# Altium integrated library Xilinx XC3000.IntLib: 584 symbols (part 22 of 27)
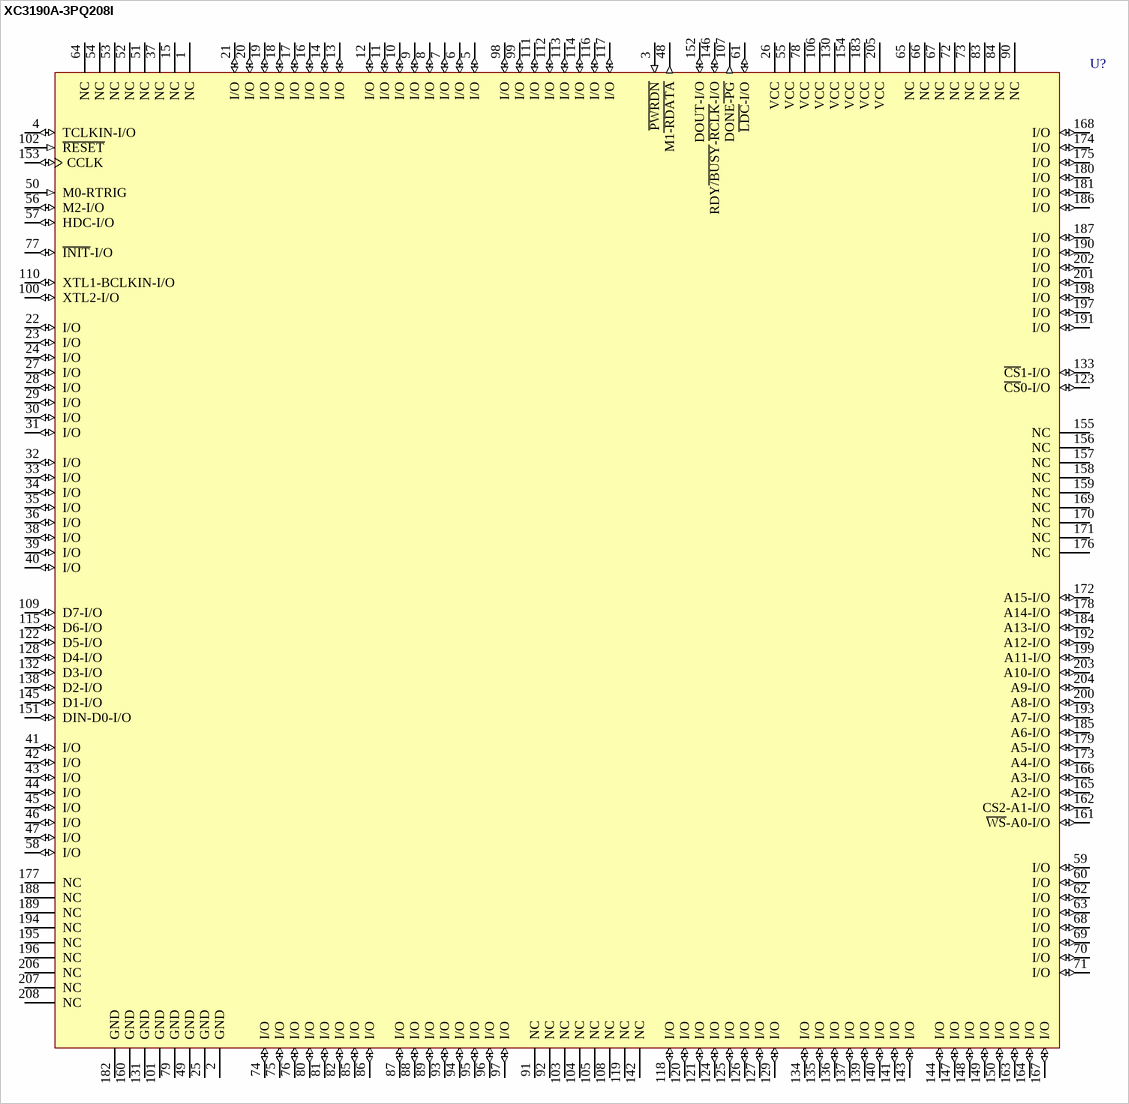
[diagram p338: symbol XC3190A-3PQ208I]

## XC3190A-3PQ208I
designator U?
Logic Cell Array with 320 CLBs, with 144 I/O Pins, 208-Pin PQFP, Industrial Grade; ComponentAvailability: Not for New Design
footprint PQ208_N (Shrink QFP, 208-Leads, Body 28x28mm, Pitch 0.5mm, IPC Medium Density)
footprint PQ208_L (Shrink QFP, 208-Leads, Body 28x28mm, Pitch 0.5mm, IPC High Density)
footprint PQ208_M (Shrink QFP, 208-Leads, Body 28x28mm, Pitch 0.5mm, IPC Low Density)
3D model XC3190A-PQ208 (208-Pin Plastic Quad Flat Pack (PQ208))
pins: 1 NC, 2 GND (power), 3 ~{PWRDN} (in), 4 TCLKIN-I/O (io), 5 I/O (io), 6 I/O (io), 7 I/O (io), 8 I/O (io), 9 I/O (io), 10 I/O (io), 11 I/O (io), 12 I/O (io), 13 I/O (io), 14 I/O (io), 15 NC, 16 I/O (io), 17 I/O (io), 18 I/O (io), 19 I/O (io), 20 I/O (io), 21 I/O (io), 22 I/O (io), 23 I/O (io), 24 I/O (io), 25 GND (power), 26 VCC (power), 27 I/O (io), 28 I/O (io), 29 I/O (io), 30 I/O (io), 31 I/O (io), 32 I/O (io), 33 I/O (io), 34 I/O (io), 35 I/O (io), 36 I/O (io), 37 NC, 38 I/O (io), 39 I/O (io), 40 I/O (io), 41 I/O (io), 42 I/O (io), 43 I/O (io), 44 I/O (io), 45 I/O (io), 46 I/O (io), 47 I/O (io), 48 M1~{-RDATA} (out), 49 GND (power), 50 M0-RTRIG (in), 51 NC, 52 NC, 53 NC, 54 NC, 55 VCC (power), 56 M2-I/O (io), 57 HDC-I/O (io), 58 I/O (io), 59 I/O (io), 60 I/O (io), 61 ~{LDC}-I/O (io), 62 I/O (io), 63 I/O (io), 64 NC, 65 NC, 66 NC, 67 NC, 68 I/O (io), 69 I/O (io), 70 I/O (io), 71 I/O (io), 72 NC, 73 NC, 74 I/O (io), 75 I/O (io), 76 I/O (io), 77 ~{INIT}-I/O (io), 78 VCC (power), 79 GND (power), 80 I/O (io), 81 I/O (io), 82 I/O (io), 83 NC, 84 NC, 85 I/O (io), 86 I/O (io), 87 I/O (io), 88 I/O (io), 89 I/O (io), 90 NC, 91 NC, 92 NC, 93 I/O (io), 94 I/O (io), 95 I/O (io), 96 I/O (io), 97 I/O (io), 98 I/O (io), 99 I/O (io), 100 XTL2-I/O (io), 101 GND (power), 102 ~{RESET} (in), 103 NC, 104 NC, 105 NC, 106 VCC (power), 107 DONE~{-PG} (out), 108 NC, 109 D7-I/O (io), 110 XTL1-BCLKIN-I/O (io), 111 I/O (io), 112 I/O (io), 113 I/O (io), 114 I/O (io), 115 D6-I/O (io), 116 I/O (io), 117 I/O (io), 118 I/O (io), 119 NC, 120 I/O (io), 121 I/O (io), 122 D5-I/O (io), 123 ~{CS}0-I/O (io), 124 I/O (io), 125 I/O (io), 126 I/O (io), 127 I/O (io), 128 D4-I/O (io), 129 I/O (io), 130 VCC (power), 131 GND (power), 132 D3-I/O (io), 133 ~{CS}1-I/O (io), 134 I/O (io), 135 I/O (io), 136 I/O (io), 137 I/O (io), 138 D2-I/O (io), 139 I/O (io), 140 I/O (io), 141 I/O (io), 142 NC, 143 I/O (io), 144 I/O (io), 145 D1-I/O (io), 146 RDY~{/BUSY}-~{RCLK}-I/O (io), 147 I/O (io), 148 I/O (io), 149 I/O (io), 150 I/O (io), 151 DIN-D0-I/O (io), 152 DOUT-I/O (io), 153 CCLK (io), 154 VCC (power), 155 NC, 156 NC, 157 NC, 158 NC, 159 NC, 160 GND (power), 161 ~{WS}-A0-I/O (io), 162 CS2-A1-I/O (io), 163 I/O (io), 164 I/O (io), 165 A2-I/O (io), 166 A3-I/O (io), 167 I/O (io), 168 I/O (io), 169 NC, 170 NC, 171 NC, 172 A15-I/O (io), 173 A4-I/O (io), 174 I/O (io), 175 I/O (io), 176 NC, 177 NC, 178 A14-I/O (io), 179 A5-I/O (io), 180 I/O (io), 181 I/O (io), 182 GND (power), 183 VCC (power), 184 A13-I/O (io), 185 A6-I/O (io), 186 I/O (io), 187 I/O (io), 188 NC, 189 NC, 190 I/O (io), 191 I/O (io), 192 A12-I/O (io), 193 A7-I/O (io), 194 NC, 195 NC, 196 NC, 197 I/O (io), 198 I/O (io), 199 A11-I/O (io), 200 A8-I/O (io), 201 I/O (io), 202 I/O (io), 203 A10-I/O (io), 204 A9-I/O (io), 205 VCC (power), 206 NC, 207 NC, 208 NC

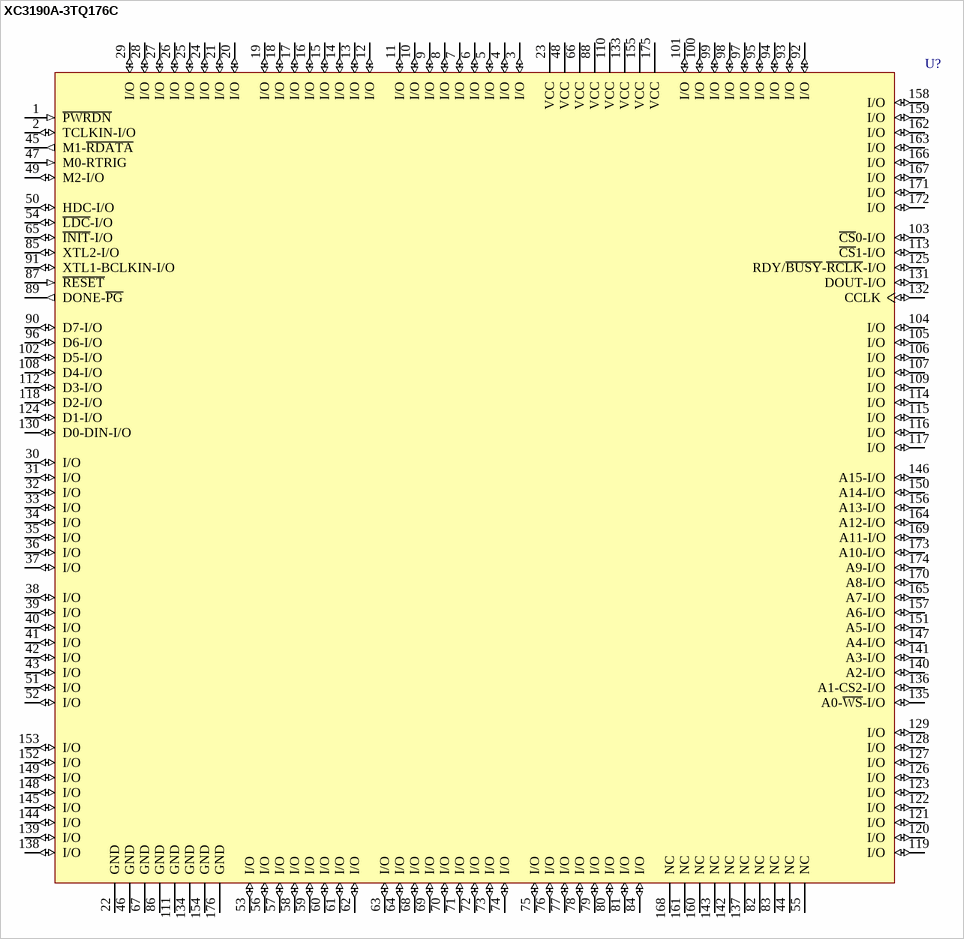
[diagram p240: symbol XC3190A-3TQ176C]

## XC3190A-3TQ176C
designator U?
Logic Cell Array with 320 CLBs, with 144 I/O Pins, 176-Pin TQFP, Commercial Grade; ComponentAvailability: Not for New Design
footprint TQ176_N (Thin QFP, 176-Leads, Body 24x24mm, Pitch 0.5mm, IPC Medium Density)
footprint TQ176_L (Thin QFP, 176-Leads, Body 24x24mm, Pitch 0.5mm, IPC High Density)
footprint TQ176_M (Thin QFP, 176-Leads, Body 24x24mm, Pitch 0.5mm, IPC Low Density)
3D model XC3190A-TQ176 (176-Pin Thin Quad Flat Pack (TQ176))
pins: 1 ~{PWRDN} (in), 2 TCLKIN-I/O (io), 3 I/O (io), 4 I/O (io), 5 I/O (io), 6 I/O (io), 7 I/O (io), 8 I/O (io), 9 I/O (io), 10 I/O (io), 11 I/O (io), 12 I/O (io), 13 I/O (io), 14 I/O (io), 15 I/O (io), 16 I/O (io), 17 I/O (io), 18 I/O (io), 19 I/O (io), 20 I/O (io), 21 I/O (io), 22 GND (power), 23 VCC (power), 24 I/O (io), 25 I/O (io), 26 I/O (io), 27 I/O (io), 28 I/O (io), 29 I/O (io), 30 I/O (io), 31 I/O (io), 32 I/O (io), 33 I/O (io), 34 I/O (io), 35 I/O (io), 36 I/O (io), 37 I/O (io), 38 I/O (io), 39 I/O (io), 40 I/O (io), 41 I/O (io), 42 I/O (io), 43 I/O (io), 44 NC, 45 M1-~{RDATA} (out), 46 GND (power), 47 M0-RTRIG (in), 48 VCC (power), 49 M2-I/O (io), 50 HDC-I/O (io), 51 I/O (io), 52 I/O (io), 53 I/O (io), 54 ~{LDC}-I/O (io), 55 NC, 56 I/O (io), 57 I/O (io), 58 I/O (io), 59 I/O (io), 60 I/O (io), 61 I/O (io), 62 I/O (io), 63 I/O (io), 64 I/O (io), 65 ~{INIT}-I/O (io), 66 VCC (power), 67 GND (power), 68 I/O (io), 69 I/O (io), 70 I/O (io), 71 I/O (io), 72 I/O (io), 73 I/O (io), 74 I/O (io), 75 I/O (io), 76 I/O (io), 77 I/O (io), 78 I/O (io), 79 I/O (io), 80 I/O (io), 81 I/O (io), 82 NC, 83 NC, 84 I/O (io), 85 XTL2-I/O (io), 86 GND (power), 87 ~{RESET} (in), 88 VCC (power), 89 DONE-~{PG} (out), 90 D7-I/O (io), 91 XTL1-BCLKIN-I/O (io), 92 I/O (io), 93 I/O (io), 94 I/O (io), 95 I/O (io), 96 D6-I/O (io), 97 I/O (io), 98 I/O (io), 99 I/O (io), 100 I/O (io), 101 I/O (io), 102 D5-I/O (io), 103 ~{CS}0-I/O (io), 104 I/O (io), 105 I/O (io), 106 I/O (io), 107 I/O (io), 108 D4-I/O (io), 109 I/O (io), 110 VCC (power), 111 GND (power), 112 D3-I/O (io), 113 ~{CS}1-I/O (io), 114 I/O (io), 115 I/O (io), 116 I/O (io), 117 I/O (io), 118 D2-I/O (io), 119 I/O (io), 120 I/O (io), 121 I/O (io), 122 I/O (io), 123 I/O (io), 124 D1-I/O (io), 125 RDY/~{BUSY}-~{RCLK}-I/O (io), 126 I/O (io), 127 I/O (io), 128 I/O (io), 129 I/O (io), 130 D0-DIN-I/O (io), 131 DOUT-I/O (io), 132 CCLK (io), 133 VCC (power), 134 GND (power), 135 A0-~{WS}-I/O (io), 136 A1-CS2-I/O (io), 137 NC, 138 I/O (io), 139 I/O (io), 140 A2-I/O (io), 141 A3-I/O (io), 142 NC, 143 NC, 144 I/O (io), 145 I/O (io), 146 A15-I/O (io), 147 A4-I/O (io), 148 I/O (io), 149 I/O (io), 150 A14-I/O (io), 151 A5-I/O (io), 152 I/O (io), 153 I/O (io), 154 GND (power), 155 VCC (power), 156 A13-I/O (io), 157 A6-I/O (io), 158 I/O (io), 159 I/O (io), 160 NC, 161 NC, 162 I/O (io), 163 I/O (io), 164 A12-I/O (io), 165 A7-I/O (io), 166 I/O (io), 167 I/O (io), 168 NC, 169 A11-I/O (io), 170 A8-I/O (io), 171 I/O (io), 172 I/O (io), 173 A10-I/O (io), 174 A9-I/O (io), 175 VCC (power), 176 GND (power)

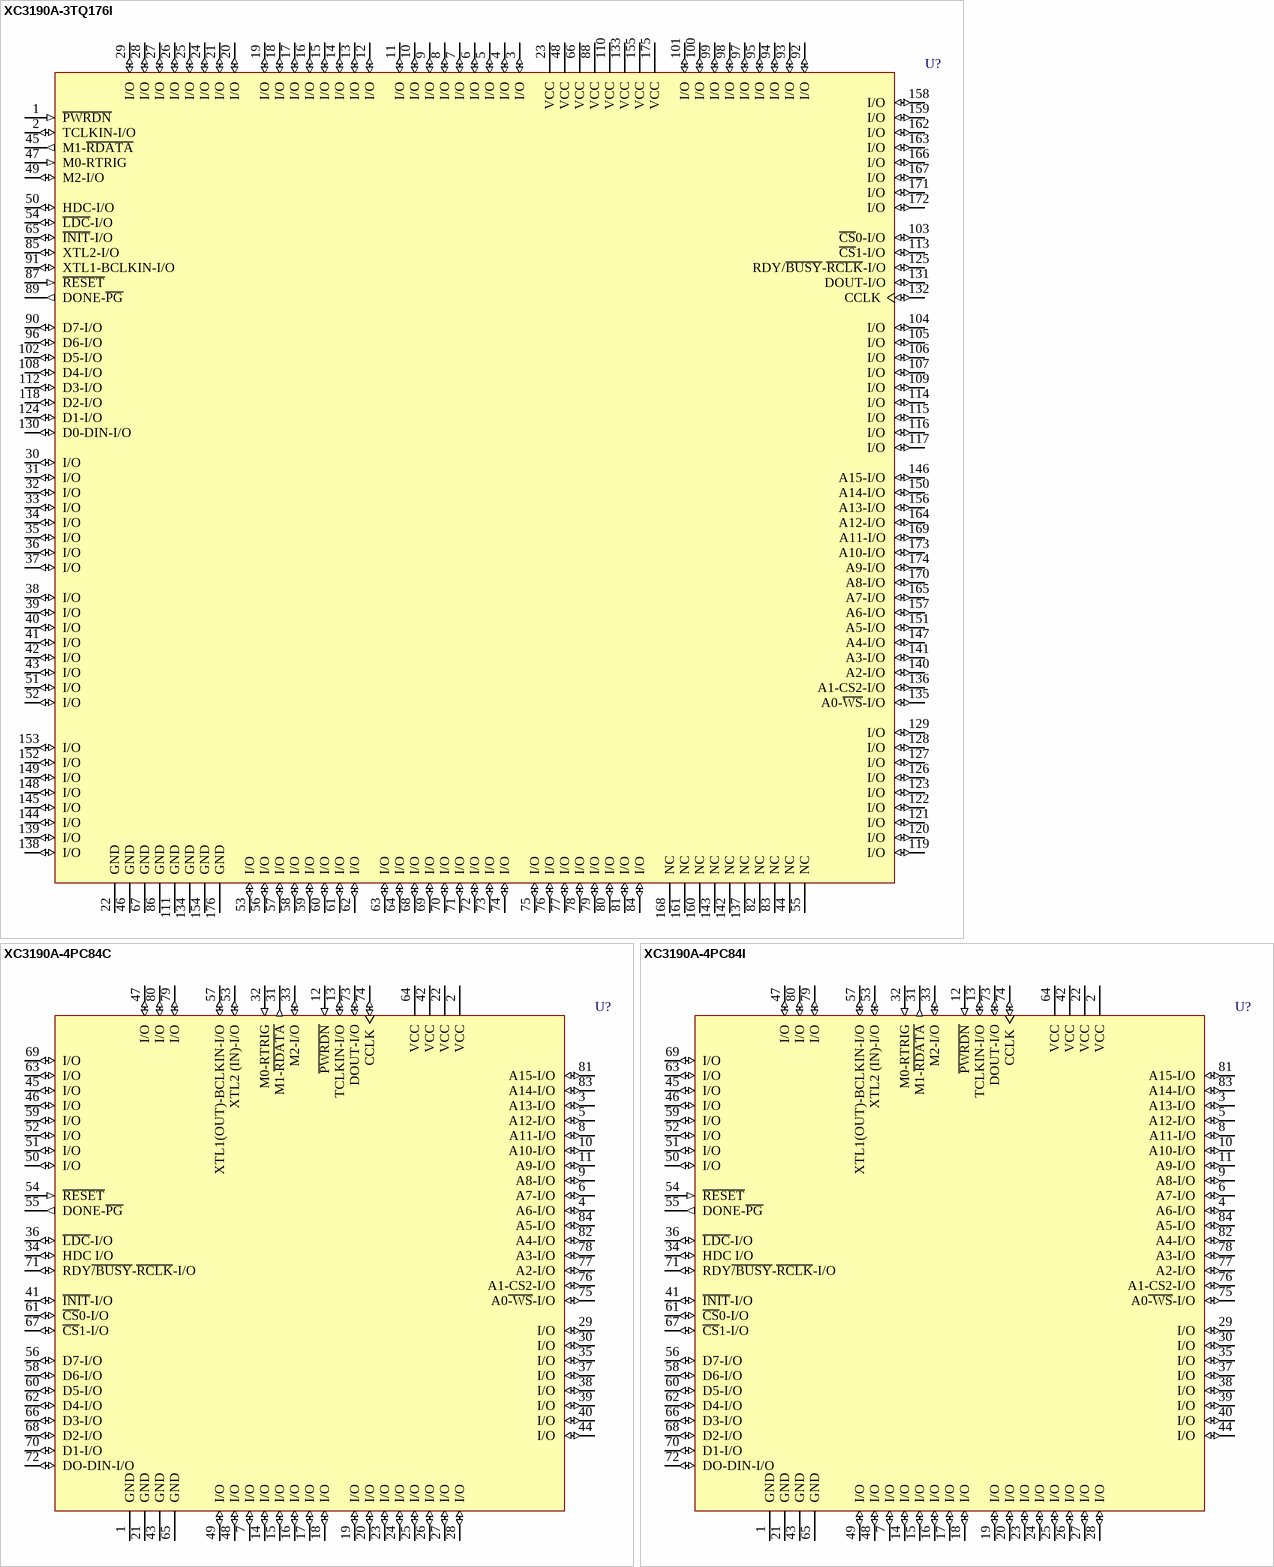
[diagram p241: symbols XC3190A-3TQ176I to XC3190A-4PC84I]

## XC3190A-3TQ176I
designator U?
Logic Cell Array with 320 CLBs, with 144 I/O Pins, 176-Pin TQFP, Industrial Grade; ComponentAvailability: Not for New Design
footprint TQ176_N (Thin QFP, 176-Leads, Body 24x24mm, Pitch 0.5mm, IPC Medium Density)
footprint TQ176_L (Thin QFP, 176-Leads, Body 24x24mm, Pitch 0.5mm, IPC High Density)
footprint TQ176_M (Thin QFP, 176-Leads, Body 24x24mm, Pitch 0.5mm, IPC Low Density)
3D model XC3190A-TQ176 (176-Pin Thin Quad Flat Pack (TQ176))
pins: 1 ~{PWRDN} (in), 2 TCLKIN-I/O (io), 3 I/O (io), 4 I/O (io), 5 I/O (io), 6 I/O (io), 7 I/O (io), 8 I/O (io), 9 I/O (io), 10 I/O (io), 11 I/O (io), 12 I/O (io), 13 I/O (io), 14 I/O (io), 15 I/O (io), 16 I/O (io), 17 I/O (io), 18 I/O (io), 19 I/O (io), 20 I/O (io), 21 I/O (io), 22 GND (power), 23 VCC (power), 24 I/O (io), 25 I/O (io), 26 I/O (io), 27 I/O (io), 28 I/O (io), 29 I/O (io), 30 I/O (io), 31 I/O (io), 32 I/O (io), 33 I/O (io), 34 I/O (io), 35 I/O (io), 36 I/O (io), 37 I/O (io), 38 I/O (io), 39 I/O (io), 40 I/O (io), 41 I/O (io), 42 I/O (io), 43 I/O (io), 44 NC, 45 M1-~{RDATA} (out), 46 GND (power), 47 M0-RTRIG (in), 48 VCC (power), 49 M2-I/O (io), 50 HDC-I/O (io), 51 I/O (io), 52 I/O (io), 53 I/O (io), 54 ~{LDC}-I/O (io), 55 NC, 56 I/O (io), 57 I/O (io), 58 I/O (io), 59 I/O (io), 60 I/O (io), 61 I/O (io), 62 I/O (io), 63 I/O (io), 64 I/O (io), 65 ~{INIT}-I/O (io), 66 VCC (power), 67 GND (power), 68 I/O (io), 69 I/O (io), 70 I/O (io), 71 I/O (io), 72 I/O (io), 73 I/O (io), 74 I/O (io), 75 I/O (io), 76 I/O (io), 77 I/O (io), 78 I/O (io), 79 I/O (io), 80 I/O (io), 81 I/O (io), 82 NC, 83 NC, 84 I/O (io), 85 XTL2-I/O (io), 86 GND (power), 87 ~{RESET} (in), 88 VCC (power), 89 DONE-~{PG} (out), 90 D7-I/O (io), 91 XTL1-BCLKIN-I/O (io), 92 I/O (io), 93 I/O (io), 94 I/O (io), 95 I/O (io), 96 D6-I/O (io), 97 I/O (io), 98 I/O (io), 99 I/O (io), 100 I/O (io), 101 I/O (io), 102 D5-I/O (io), 103 ~{CS}0-I/O (io), 104 I/O (io), 105 I/O (io), 106 I/O (io), 107 I/O (io), 108 D4-I/O (io), 109 I/O (io), 110 VCC (power), 111 GND (power), 112 D3-I/O (io), 113 ~{CS}1-I/O (io), 114 I/O (io), 115 I/O (io), 116 I/O (io), 117 I/O (io), 118 D2-I/O (io), 119 I/O (io), 120 I/O (io), 121 I/O (io), 122 I/O (io), 123 I/O (io), 124 D1-I/O (io), 125 RDY/~{BUSY}-~{RCLK}-I/O (io), 126 I/O (io), 127 I/O (io), 128 I/O (io), 129 I/O (io), 130 D0-DIN-I/O (io), 131 DOUT-I/O (io), 132 CCLK (io), 133 VCC (power), 134 GND (power), 135 A0-~{WS}-I/O (io), 136 A1-CS2-I/O (io), 137 NC, 138 I/O (io), 139 I/O (io), 140 A2-I/O (io), 141 A3-I/O (io), 142 NC, 143 NC, 144 I/O (io), 145 I/O (io), 146 A15-I/O (io), 147 A4-I/O (io), 148 I/O (io), 149 I/O (io), 150 A14-I/O (io), 151 A5-I/O (io), 152 I/O (io), 153 I/O (io), 154 GND (power), 155 VCC (power), 156 A13-I/O (io), 157 A6-I/O (io), 158 I/O (io), 159 I/O (io), 160 NC, 161 NC, 162 I/O (io), 163 I/O (io), 164 A12-I/O (io), 165 A7-I/O (io), 166 I/O (io), 167 I/O (io), 168 NC, 169 A11-I/O (io), 170 A8-I/O (io), 171 I/O (io), 172 I/O (io), 173 A10-I/O (io), 174 A9-I/O (io), 175 VCC (power), 176 GND (power)

## XC3190A-4PC84C
designator U?
Logic Cell Array with 320 CLBs, with 70 I/O Pins, 84-Pin PLCC, Commercial Grade; ComponentAvailability: Not for New Design
footprint PC84_N (Leaded Chip Carrier, 84-Leads, Body 29.3x29.3mm, Pitch 1.27mm, IPC Medium Density)
footprint PC84_L (Leaded Chip Carrier, 84-Leads, Body 29.3x29.3mm, Pitch 1.27mm, IPC High Density)
footprint PC84_M (Leaded Chip Carrier, 84-Leads, Body 29.3x29.3mm, Pitch 1.27mm, IPC Low Density)
3D model XC3190A-PC84 (84-Pin Plastic Leaded Chip Carrier (PC84))
pins: 1 GND (power), 2 VCC (power), 3 A13-I/O (io), 4 A6-I/O (io), 5 A12-I/O (io), 6 A7-I/O (io), 7 I/O (io), 8 A11-I/O (io), 9 A8-I/O (io), 10 A10-I/O (io), 11 A9-I/O (io), 12 ~{PWRDN} (in), 13 TCLKIN-I/O (io), 14 I/O (io), 15 I/O (io), 16 I/O (io), 17 I/O (io), 18 I/O (io), 19 I/O (io), 20 I/O (io), 21 GND (power), 22 VCC (power), 23 I/O (io), 24 I/O (io), 25 I/O (io), 26 I/O (io), 27 I/O (io), 28 I/O (io), 29 I/O (io), 30 I/O (io), 31 M1-~{RDATA} (out), 32 M0-RTRIG (in), 33 M2-I/O (io), 34 HDC I/O (io), 35 I/O (io), 36 ~{LDC}-I/O (io), 37 I/O (io), 38 I/O (io), 39 I/O (io), 40 I/O (io), 41 ~{INIT}-I/O (io), 42 VCC (power), 43 GND (power), 44 I/O (io), 45 I/O (io), 46 I/O (io), 47 I/O (io), 48 I/O (io), 49 I/O (io), 50 I/O (io), 51 I/O (io), 52 I/O (io), 53 XTL2 (IN)-I/O (io), 54 ~{RESET} (in), 55 DONE-~{PG} (out), 56 D7-I/O (io), 57 XTL1(OUT)-BCLKIN-I/O (io), 58 D6-I/O (io), 59 I/O (io), 60 D5-I/O (io), 61 ~{CS}0-I/O (io), 62 D4-I/O (io), 63 I/O (io), 64 VCC (power), 65 GND (power), 66 D3-I/O (io), 67 ~{CS}1-I/O (io), 68 D2-I/O (io), 69 I/O (io), 70 D1-I/O (io), 71 RDY~{/BUSY}-~{RCLK}-I/O (io), 72 DO-DIN-I/O (io), 73 DOUT-I/O (io), 74 CCLK (io), 75 A0~{-WS}-I/O (io), 76 A1-CS2-I/O (io), 77 A2-I/O (io), 78 A3-I/O (io), 79 I/O (io), 80 I/O (io), 81 A15-I/O (io), 82 A4-I/O (io), 83 A14-I/O (io), 84 A5-I/O (io)

## XC3190A-4PC84I
designator U?
Logic Cell Array with 320 CLBs, with 70 I/O Pins, 84-Pin PLCC, Industrial Grade; ComponentAvailability: Not for New Design
footprint PC84_N (Leaded Chip Carrier, 84-Leads, Body 29.3x29.3mm, Pitch 1.27mm, IPC Medium Density)
footprint PC84_L (Leaded Chip Carrier, 84-Leads, Body 29.3x29.3mm, Pitch 1.27mm, IPC High Density)
footprint PC84_M (Leaded Chip Carrier, 84-Leads, Body 29.3x29.3mm, Pitch 1.27mm, IPC Low Density)
3D model XC3190A-PC84 (84-Pin Plastic Leaded Chip Carrier (PC84))
pins: 1 GND (power), 2 VCC (power), 3 A13-I/O (io), 4 A6-I/O (io), 5 A12-I/O (io), 6 A7-I/O (io), 7 I/O (io), 8 A11-I/O (io), 9 A8-I/O (io), 10 A10-I/O (io), 11 A9-I/O (io), 12 ~{PWRDN} (in), 13 TCLKIN-I/O (io), 14 I/O (io), 15 I/O (io), 16 I/O (io), 17 I/O (io), 18 I/O (io), 19 I/O (io), 20 I/O (io), 21 GND (power), 22 VCC (power), 23 I/O (io), 24 I/O (io), 25 I/O (io), 26 I/O (io), 27 I/O (io), 28 I/O (io), 29 I/O (io), 30 I/O (io), 31 M1-~{RDATA} (out), 32 M0-RTRIG (in), 33 M2-I/O (io), 34 HDC I/O (io), 35 I/O (io), 36 ~{LDC}-I/O (io), 37 I/O (io), 38 I/O (io), 39 I/O (io), 40 I/O (io), 41 ~{INIT}-I/O (io), 42 VCC (power), 43 GND (power), 44 I/O (io), 45 I/O (io), 46 I/O (io), 47 I/O (io), 48 I/O (io), 49 I/O (io), 50 I/O (io), 51 I/O (io), 52 I/O (io), 53 XTL2 (IN)-I/O (io), 54 ~{RESET} (in), 55 DONE-~{PG} (out), 56 D7-I/O (io), 57 XTL1(OUT)-BCLKIN-I/O (io), 58 D6-I/O (io), 59 I/O (io), 60 D5-I/O (io), 61 ~{CS}0-I/O (io), 62 D4-I/O (io), 63 I/O (io), 64 VCC (power), 65 GND (power), 66 D3-I/O (io), 67 ~{CS}1-I/O (io), 68 D2-I/O (io), 69 I/O (io), 70 D1-I/O (io), 71 RDY~{/BUSY}-~{RCLK}-I/O (io), 72 DO-DIN-I/O (io), 73 DOUT-I/O (io), 74 CCLK (io), 75 A0~{-WS}-I/O (io), 76 A1-CS2-I/O (io), 77 A2-I/O (io), 78 A3-I/O (io), 79 I/O (io), 80 I/O (io), 81 A15-I/O (io), 82 A4-I/O (io), 83 A14-I/O (io), 84 A5-I/O (io)

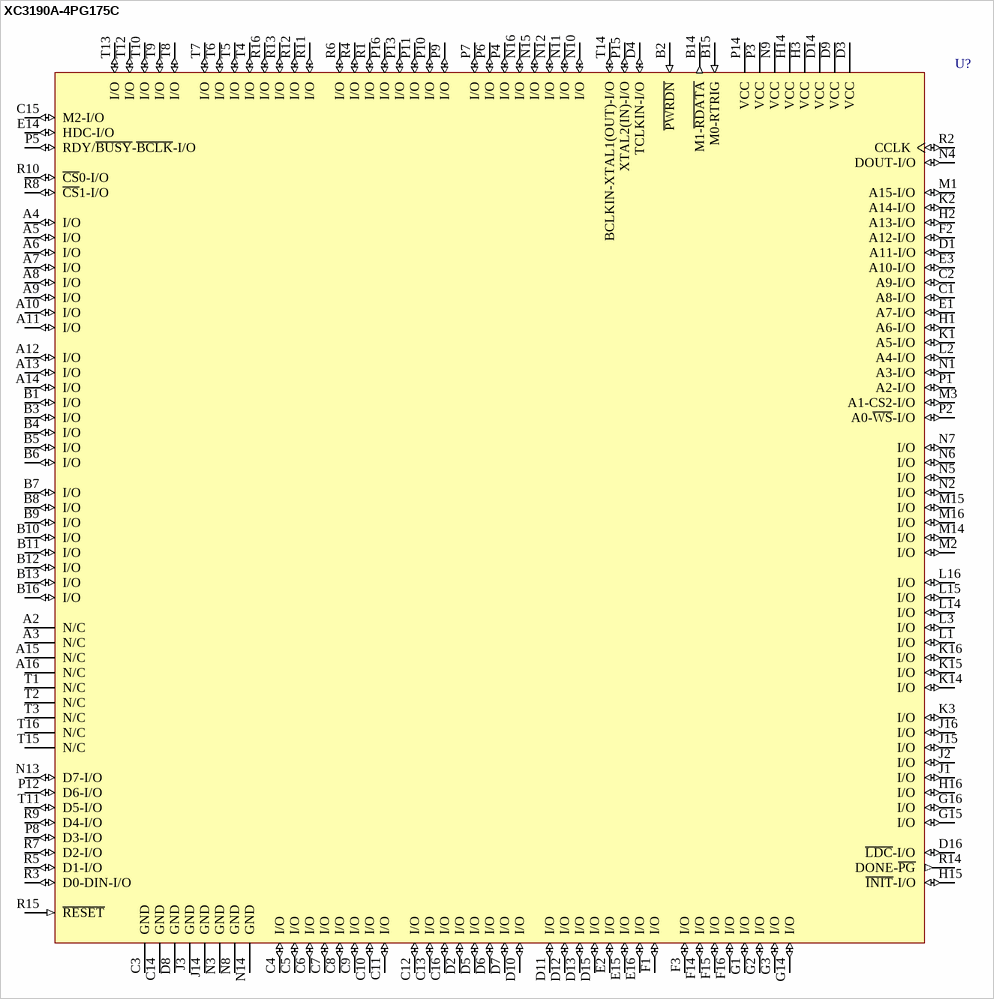
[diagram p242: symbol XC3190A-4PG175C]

## XC3190A-4PG175C
designator U?
Logic Cell Array with 320 CLBs, with 144 I/O Pins, 175-Pin PGA, Commercial Grade; ComponentAvailability: Not for New Design
footprint PG175 (PGA, 175-Leads, Body 42x42mm, Pitch 2.54mm)
3D model XC3190A-PG175 (175-Pin Ceramic Pin Grid Array (PG175))
pins: A2 N/C, A3 N/C, A4 I/O (io), A5 I/O (io), A6 I/O (io), A7 I/O (io), A8 I/O (io), A9 I/O (io), A10 I/O (io), A11 I/O (io), A12 I/O (io), A13 I/O (io), A14 I/O (io), A15 N/C, A16 N/C, B1 I/O (io), B2 ~{PWRDN} (in), B3 I/O (io), B4 I/O (io), B5 I/O (io), B6 I/O (io), B7 I/O (io), B8 I/O (io), B9 I/O (io), B10 I/O (io), B11 I/O (io), B12 I/O (io), B13 I/O (io), B14 M1-~{RDATA} (out), B15 M0-RTRIG (in), B16 I/O (io), C1 A8-I/O (io), C2 A9-I/O (io), C3 GND (power), C4 I/O (io), C5 I/O (io), C6 I/O (io), C7 I/O (io), C8 I/O (io), C9 I/O (io), C10 I/O (io), C11 I/O (io), C12 I/O (io), C13 I/O (io), C14 GND (power), C15 M2-I/O (io), C16 I/O (io), D1 A11-I/O (io), D2 I/O (io), D3 VCC (power), D4 TCLKIN-I/O (io), D5 I/O (io), D6 I/O (io), D7 I/O (io), D8 GND (power), D9 VCC (power), D10 I/O (io), D11 I/O (io), D12 I/O (io), D13 I/O (io), D14 VCC (power), D15 I/O (io), D16 ~{LDC}-I/O (io), E1 A7-I/O (io), E2 I/O (io), E3 A10-I/O (io), E14 HDC-I/O (io), E15 I/O (io), E16 I/O (io), F1 I/O (io), F2 A12-I/O (io), F3 I/O (io), F14 I/O (io), F15 I/O (io), F16 I/O (io), G1 I/O (io), G2 I/O (io), G3 I/O (io), G14 I/O (io), G15 I/O (io), G16 I/O (io), H1 A6-I/O (io), H2 A13-I/O (io), H3 VCC (power), H14 VCC (power), H15 ~{INIT}-I/O (io), H16 I/O (io), J1 I/O (io), J2 I/O (io), J3 GND (power), J14 GND (power), J15 I/O (io), J16 I/O (io), K1 A5-I/O (io), K2 A14-I/O (io), K3 I/O (io), K14 I/O (io), K15 I/O (io), K16 I/O (io), L1 I/O (io), L2 A4-I/O (io), L3 I/O (io), L14 I/O (io), L15 I/O (io), L16 I/O (io), M1 A15-I/O (io), M2 I/O (io), M3 A1-CS2-I/O (io), M14 I/O (io), M15 I/O (io), M16 I/O (io), N1 A3-I/O (io), N2 I/O (io), N3 GND (power), N4 DOUT-I/O (io), N5 I/O (io), N6 I/O (io), N7 I/O (io), N8 GND (power), N9 VCC (power), N10 I/O (io), N11 I/O (io), N12 I/O (io), N13 D7-I/O (io), N14 GND (power), N15 I/O (io), N16 I/O (io), P1 A2-I/O (io), P2 A0-~{WS}-I/O (io), P3 VCC (power), P4 I/O (io), P5 RDY/~{BUSY}-~{BCLK}-I/O (io), P6 I/O (io), P7 I/O (io), P8 D3-I/O (io), P9 I/O (io), P10 I/O (io), P11 I/O (io), P12 D6-I/O (io), P13 I/O (io), P14 VCC (power), P15 XTAL2(IN)-I/O (io), P16 I/O (io), R1 I/O (io), R2 CCLK (io), R3 D0-DIN-I/O (io), R4 I/O (io), R5 D1-I/O (io), R6 I/O (io), R7 D2-I/O (io), R8 ~{CS}1-I/O (io), R9 D4-I/O (io), R10 ~{CS}0-I/O (io), R11 I/O (io), R12 I/O (io), R13 I/O (io), R14 DONE-~{PG} (out), R15 ~{RESET} (in), R16 I/O (io), T1 N/C, T2 N/C, T3 N/C, T4 I/O (io), T5 I/O (io), T6 I/O (io), T7 I/O (io), T8 I/O (io), T9 I/O (io), T10 I/O (io), T11 D5-I/O (io), T12 I/O (io), T13 I/O (io), T14 BCLKIN-XTAL1(OUT)-I/O (io), T15 N/C, T16 N/C

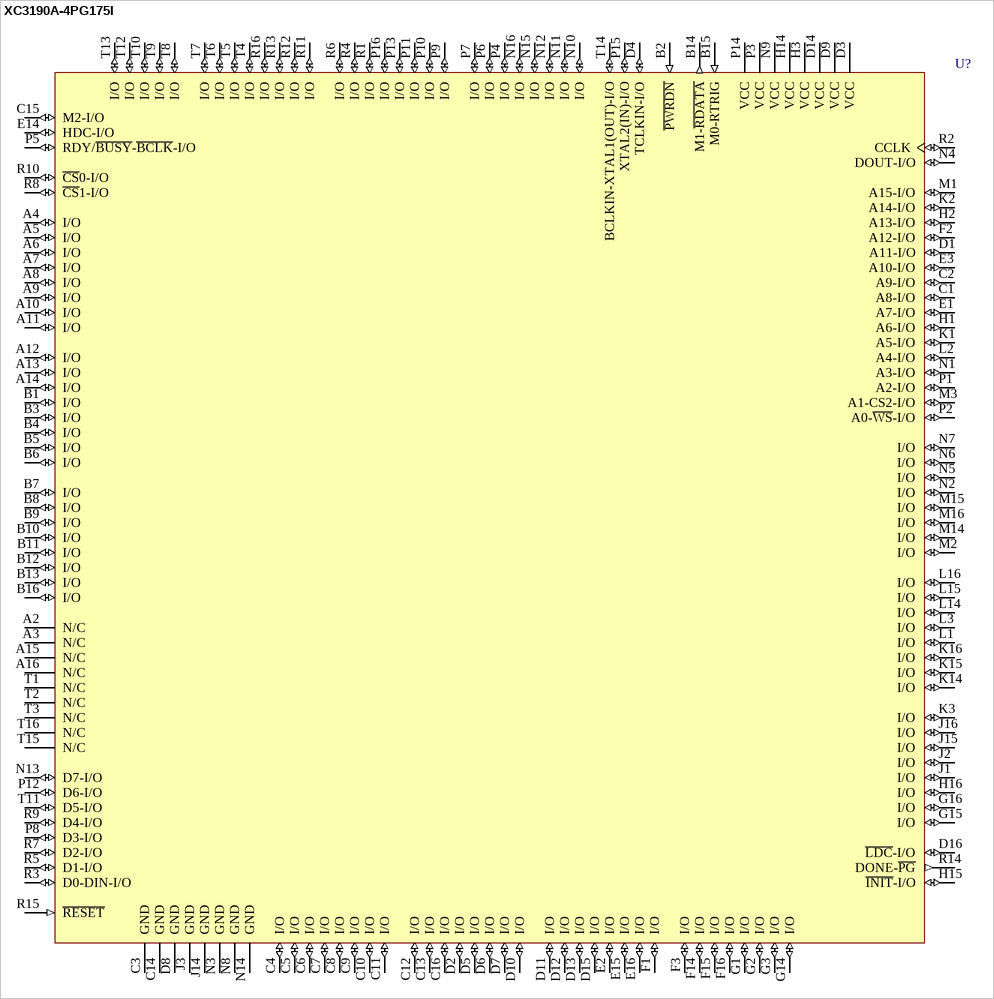
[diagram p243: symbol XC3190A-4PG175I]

## XC3190A-4PG175I
designator U?
Logic Cell Array with 320 CLBs, with 144 I/O Pins, 175-Pin PGA, Industrial Grade; ComponentAvailability: Not for New Design
footprint PG175 (PGA, 175-Leads, Body 42x42mm, Pitch 2.54mm)
3D model XC3190A-PG175 (175-Pin Ceramic Pin Grid Array (PG175))
pins: A2 N/C, A3 N/C, A4 I/O (io), A5 I/O (io), A6 I/O (io), A7 I/O (io), A8 I/O (io), A9 I/O (io), A10 I/O (io), A11 I/O (io), A12 I/O (io), A13 I/O (io), A14 I/O (io), A15 N/C, A16 N/C, B1 I/O (io), B2 ~{PWRDN} (in), B3 I/O (io), B4 I/O (io), B5 I/O (io), B6 I/O (io), B7 I/O (io), B8 I/O (io), B9 I/O (io), B10 I/O (io), B11 I/O (io), B12 I/O (io), B13 I/O (io), B14 M1-~{RDATA} (out), B15 M0-RTRIG (in), B16 I/O (io), C1 A8-I/O (io), C2 A9-I/O (io), C3 GND (power), C4 I/O (io), C5 I/O (io), C6 I/O (io), C7 I/O (io), C8 I/O (io), C9 I/O (io), C10 I/O (io), C11 I/O (io), C12 I/O (io), C13 I/O (io), C14 GND (power), C15 M2-I/O (io), C16 I/O (io), D1 A11-I/O (io), D2 I/O (io), D3 VCC (power), D4 TCLKIN-I/O (io), D5 I/O (io), D6 I/O (io), D7 I/O (io), D8 GND (power), D9 VCC (power), D10 I/O (io), D11 I/O (io), D12 I/O (io), D13 I/O (io), D14 VCC (power), D15 I/O (io), D16 ~{LDC}-I/O (io), E1 A7-I/O (io), E2 I/O (io), E3 A10-I/O (io), E14 HDC-I/O (io), E15 I/O (io), E16 I/O (io), F1 I/O (io), F2 A12-I/O (io), F3 I/O (io), F14 I/O (io), F15 I/O (io), F16 I/O (io), G1 I/O (io), G2 I/O (io), G3 I/O (io), G14 I/O (io), G15 I/O (io), G16 I/O (io), H1 A6-I/O (io), H2 A13-I/O (io), H3 VCC (power), H14 VCC (power), H15 ~{INIT}-I/O (io), H16 I/O (io), J1 I/O (io), J2 I/O (io), J3 GND (power), J14 GND (power), J15 I/O (io), J16 I/O (io), K1 A5-I/O (io), K2 A14-I/O (io), K3 I/O (io), K14 I/O (io), K15 I/O (io), K16 I/O (io), L1 I/O (io), L2 A4-I/O (io), L3 I/O (io), L14 I/O (io), L15 I/O (io), L16 I/O (io), M1 A15-I/O (io), M2 I/O (io), M3 A1-CS2-I/O (io), M14 I/O (io), M15 I/O (io), M16 I/O (io), N1 A3-I/O (io), N2 I/O (io), N3 GND (power), N4 DOUT-I/O (io), N5 I/O (io), N6 I/O (io), N7 I/O (io), N8 GND (power), N9 VCC (power), N10 I/O (io), N11 I/O (io), N12 I/O (io), N13 D7-I/O (io), N14 GND (power), N15 I/O (io), N16 I/O (io), P1 A2-I/O (io), P2 A0-~{WS}-I/O (io), P3 VCC (power), P4 I/O (io), P5 RDY/~{BUSY}-~{BCLK}-I/O (io), P6 I/O (io), P7 I/O (io), P8 D3-I/O (io), P9 I/O (io), P10 I/O (io), P11 I/O (io), P12 D6-I/O (io), P13 I/O (io), P14 VCC (power), P15 XTAL2(IN)-I/O (io), P16 I/O (io), R1 I/O (io), R2 CCLK (io), R3 D0-DIN-I/O (io), R4 I/O (io), R5 D1-I/O (io), R6 I/O (io), R7 D2-I/O (io), R8 ~{CS}1-I/O (io), R9 D4-I/O (io), R10 ~{CS}0-I/O (io), R11 I/O (io), R12 I/O (io), R13 I/O (io), R14 DONE-~{PG} (out), R15 ~{RESET} (in), R16 I/O (io), T1 N/C, T2 N/C, T3 N/C, T4 I/O (io), T5 I/O (io), T6 I/O (io), T7 I/O (io), T8 I/O (io), T9 I/O (io), T10 I/O (io), T11 D5-I/O (io), T12 I/O (io), T13 I/O (io), T14 BCLKIN-XTAL1(OUT)-I/O (io), T15 N/C, T16 N/C

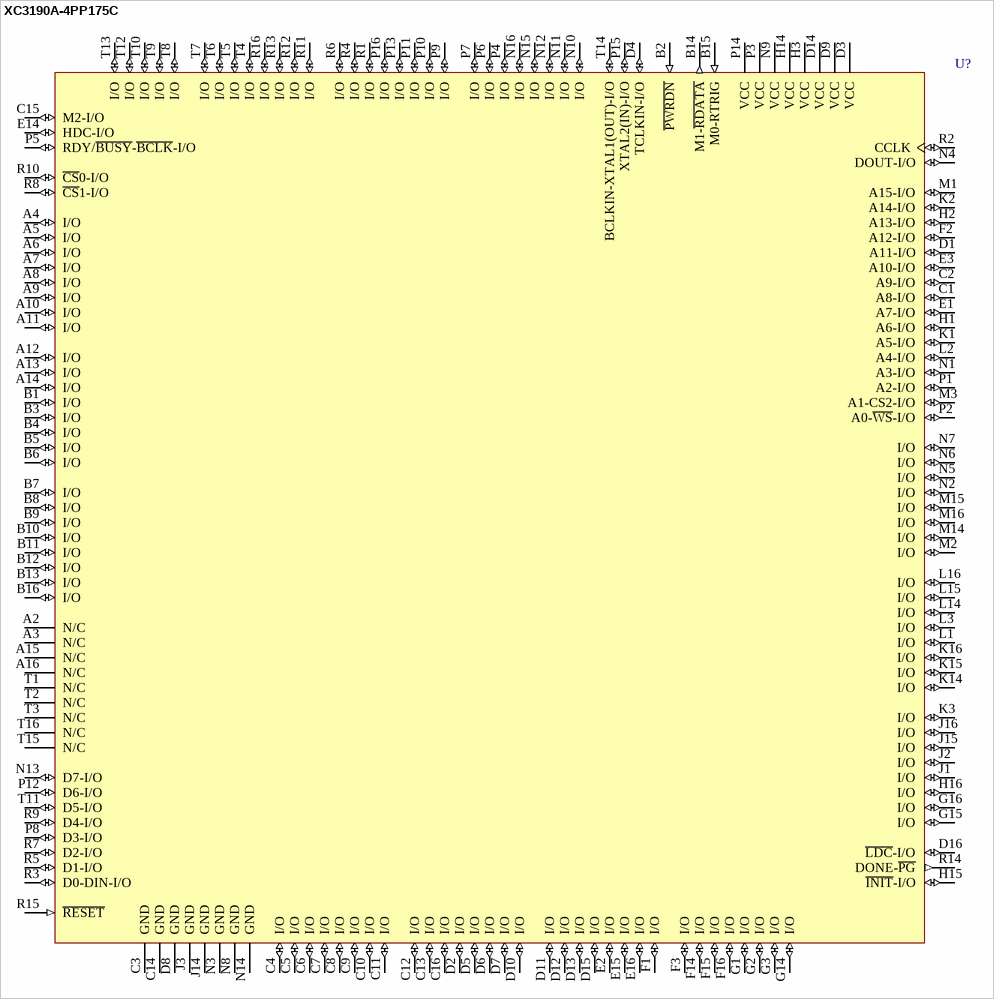
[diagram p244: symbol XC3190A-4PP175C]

## XC3190A-4PP175C
designator U?
Logic Cell Array with 320 CLBs, with 144 I/O Pins, 175-Pin PGA, Commercial Grade; ComponentAvailability: Not for New Design
footprint PP175 (PGA, 175-Leads, Body 42x42mm, Pitch 2.54mm)
3D model XC3190A-PP175 (175-Pin Plastic Pin Grid Array (PP175))
pins: A2 N/C, A3 N/C, A4 I/O (io), A5 I/O (io), A6 I/O (io), A7 I/O (io), A8 I/O (io), A9 I/O (io), A10 I/O (io), A11 I/O (io), A12 I/O (io), A13 I/O (io), A14 I/O (io), A15 N/C, A16 N/C, B1 I/O (io), B2 ~{PWRDN} (in), B3 I/O (io), B4 I/O (io), B5 I/O (io), B6 I/O (io), B7 I/O (io), B8 I/O (io), B9 I/O (io), B10 I/O (io), B11 I/O (io), B12 I/O (io), B13 I/O (io), B14 M1-~{RDATA} (out), B15 M0-RTRIG (in), B16 I/O (io), C1 A8-I/O (io), C2 A9-I/O (io), C3 GND (power), C4 I/O (io), C5 I/O (io), C6 I/O (io), C7 I/O (io), C8 I/O (io), C9 I/O (io), C10 I/O (io), C11 I/O (io), C12 I/O (io), C13 I/O (io), C14 GND (power), C15 M2-I/O (io), C16 I/O (io), D1 A11-I/O (io), D2 I/O (io), D3 VCC (power), D4 TCLKIN-I/O (io), D5 I/O (io), D6 I/O (io), D7 I/O (io), D8 GND (power), D9 VCC (power), D10 I/O (io), D11 I/O (io), D12 I/O (io), D13 I/O (io), D14 VCC (power), D15 I/O (io), D16 ~{LDC}-I/O (io), E1 A7-I/O (io), E2 I/O (io), E3 A10-I/O (io), E14 HDC-I/O (io), E15 I/O (io), E16 I/O (io), F1 I/O (io), F2 A12-I/O (io), F3 I/O (io), F14 I/O (io), F15 I/O (io), F16 I/O (io), G1 I/O (io), G2 I/O (io), G3 I/O (io), G14 I/O (io), G15 I/O (io), G16 I/O (io), H1 A6-I/O (io), H2 A13-I/O (io), H3 VCC (power), H14 VCC (power), H15 ~{INIT}-I/O (io), H16 I/O (io), J1 I/O (io), J2 I/O (io), J3 GND (power), J14 GND (power), J15 I/O (io), J16 I/O (io), K1 A5-I/O (io), K2 A14-I/O (io), K3 I/O (io), K14 I/O (io), K15 I/O (io), K16 I/O (io), L1 I/O (io), L2 A4-I/O (io), L3 I/O (io), L14 I/O (io), L15 I/O (io), L16 I/O (io), M1 A15-I/O (io), M2 I/O (io), M3 A1-CS2-I/O (io), M14 I/O (io), M15 I/O (io), M16 I/O (io), N1 A3-I/O (io), N2 I/O (io), N3 GND (power), N4 DOUT-I/O (io), N5 I/O (io), N6 I/O (io), N7 I/O (io), N8 GND (power), N9 VCC (power), N10 I/O (io), N11 I/O (io), N12 I/O (io), N13 D7-I/O (io), N14 GND (power), N15 I/O (io), N16 I/O (io), P1 A2-I/O (io), P2 A0-~{WS}-I/O (io), P3 VCC (power), P4 I/O (io), P5 RDY/~{BUSY}-~{BCLK}-I/O (io), P6 I/O (io), P7 I/O (io), P8 D3-I/O (io), P9 I/O (io), P10 I/O (io), P11 I/O (io), P12 D6-I/O (io), P13 I/O (io), P14 VCC (power), P15 XTAL2(IN)-I/O (io), P16 I/O (io), R1 I/O (io), R2 CCLK (io), R3 D0-DIN-I/O (io), R4 I/O (io), R5 D1-I/O (io), R6 I/O (io), R7 D2-I/O (io), R8 ~{CS}1-I/O (io), R9 D4-I/O (io), R10 ~{CS}0-I/O (io), R11 I/O (io), R12 I/O (io), R13 I/O (io), R14 DONE-~{PG} (out), R15 ~{RESET} (in), R16 I/O (io), T1 N/C, T2 N/C, T3 N/C, T4 I/O (io), T5 I/O (io), T6 I/O (io), T7 I/O (io), T8 I/O (io), T9 I/O (io), T10 I/O (io), T11 D5-I/O (io), T12 I/O (io), T13 I/O (io), T14 BCLKIN-XTAL1(OUT)-I/O (io), T15 N/C, T16 N/C

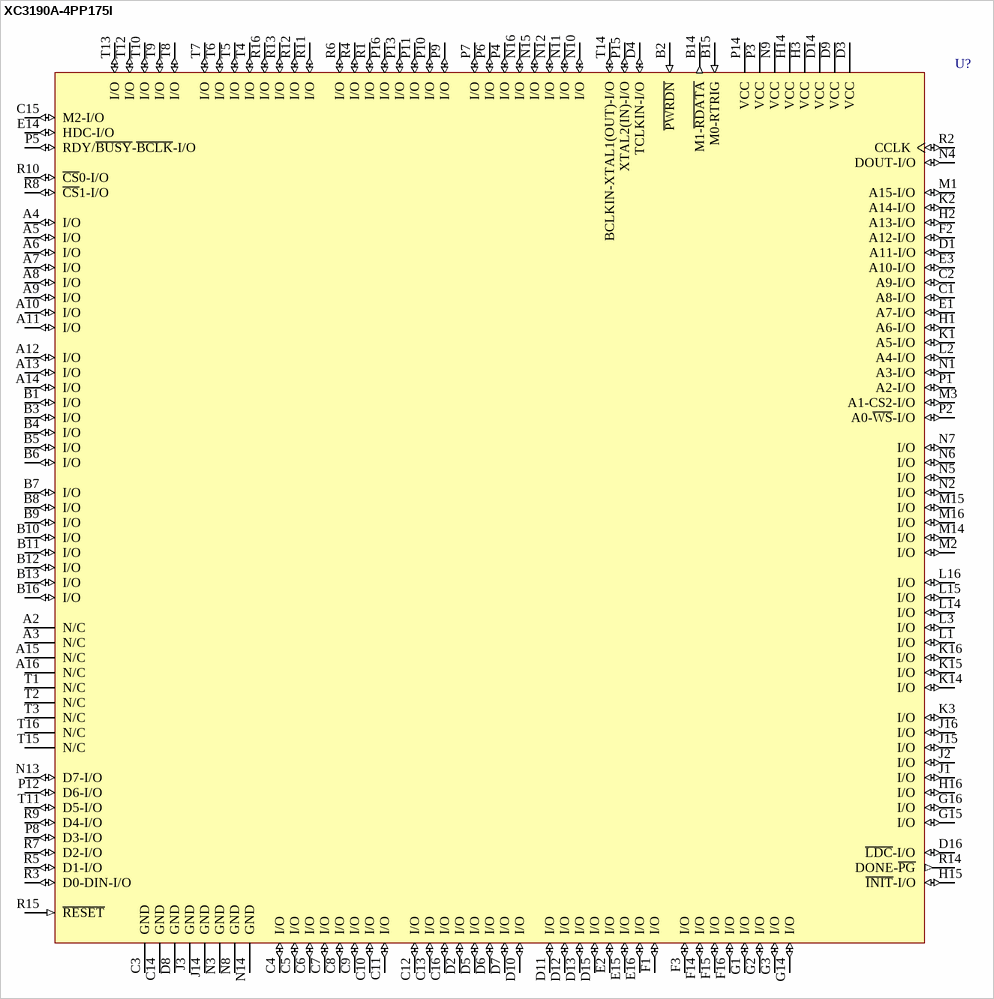
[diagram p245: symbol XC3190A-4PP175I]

## XC3190A-4PP175I
designator U?
Logic Cell Array with 320 CLBs, with 144 I/O Pins, 175-Pin PGA, Industrial Grade; ComponentAvailability: Not for New Design
footprint PP175 (PGA, 175-Leads, Body 42x42mm, Pitch 2.54mm)
3D model XC3190A-PP175 (175-Pin Plastic Pin Grid Array (PP175))
pins: A2 N/C, A3 N/C, A4 I/O (io), A5 I/O (io), A6 I/O (io), A7 I/O (io), A8 I/O (io), A9 I/O (io), A10 I/O (io), A11 I/O (io), A12 I/O (io), A13 I/O (io), A14 I/O (io), A15 N/C, A16 N/C, B1 I/O (io), B2 ~{PWRDN} (in), B3 I/O (io), B4 I/O (io), B5 I/O (io), B6 I/O (io), B7 I/O (io), B8 I/O (io), B9 I/O (io), B10 I/O (io), B11 I/O (io), B12 I/O (io), B13 I/O (io), B14 M1-~{RDATA} (out), B15 M0-RTRIG (in), B16 I/O (io), C1 A8-I/O (io), C2 A9-I/O (io), C3 GND (power), C4 I/O (io), C5 I/O (io), C6 I/O (io), C7 I/O (io), C8 I/O (io), C9 I/O (io), C10 I/O (io), C11 I/O (io), C12 I/O (io), C13 I/O (io), C14 GND (power), C15 M2-I/O (io), C16 I/O (io), D1 A11-I/O (io), D2 I/O (io), D3 VCC (power), D4 TCLKIN-I/O (io), D5 I/O (io), D6 I/O (io), D7 I/O (io), D8 GND (power), D9 VCC (power), D10 I/O (io), D11 I/O (io), D12 I/O (io), D13 I/O (io), D14 VCC (power), D15 I/O (io), D16 ~{LDC}-I/O (io), E1 A7-I/O (io), E2 I/O (io), E3 A10-I/O (io), E14 HDC-I/O (io), E15 I/O (io), E16 I/O (io), F1 I/O (io), F2 A12-I/O (io), F3 I/O (io), F14 I/O (io), F15 I/O (io), F16 I/O (io), G1 I/O (io), G2 I/O (io), G3 I/O (io), G14 I/O (io), G15 I/O (io), G16 I/O (io), H1 A6-I/O (io), H2 A13-I/O (io), H3 VCC (power), H14 VCC (power), H15 ~{INIT}-I/O (io), H16 I/O (io), J1 I/O (io), J2 I/O (io), J3 GND (power), J14 GND (power), J15 I/O (io), J16 I/O (io), K1 A5-I/O (io), K2 A14-I/O (io), K3 I/O (io), K14 I/O (io), K15 I/O (io), K16 I/O (io), L1 I/O (io), L2 A4-I/O (io), L3 I/O (io), L14 I/O (io), L15 I/O (io), L16 I/O (io), M1 A15-I/O (io), M2 I/O (io), M3 A1-CS2-I/O (io), M14 I/O (io), M15 I/O (io), M16 I/O (io), N1 A3-I/O (io), N2 I/O (io), N3 GND (power), N4 DOUT-I/O (io), N5 I/O (io), N6 I/O (io), N7 I/O (io), N8 GND (power), N9 VCC (power), N10 I/O (io), N11 I/O (io), N12 I/O (io), N13 D7-I/O (io), N14 GND (power), N15 I/O (io), N16 I/O (io), P1 A2-I/O (io), P2 A0-~{WS}-I/O (io), P3 VCC (power), P4 I/O (io), P5 RDY/~{BUSY}-~{BCLK}-I/O (io), P6 I/O (io), P7 I/O (io), P8 D3-I/O (io), P9 I/O (io), P10 I/O (io), P11 I/O (io), P12 D6-I/O (io), P13 I/O (io), P14 VCC (power), P15 XTAL2(IN)-I/O (io), P16 I/O (io), R1 I/O (io), R2 CCLK (io), R3 D0-DIN-I/O (io), R4 I/O (io), R5 D1-I/O (io), R6 I/O (io), R7 D2-I/O (io), R8 ~{CS}1-I/O (io), R9 D4-I/O (io), R10 ~{CS}0-I/O (io), R11 I/O (io), R12 I/O (io), R13 I/O (io), R14 DONE-~{PG} (out), R15 ~{RESET} (in), R16 I/O (io), T1 N/C, T2 N/C, T3 N/C, T4 I/O (io), T5 I/O (io), T6 I/O (io), T7 I/O (io), T8 I/O (io), T9 I/O (io), T10 I/O (io), T11 D5-I/O (io), T12 I/O (io), T13 I/O (io), T14 BCLKIN-XTAL1(OUT)-I/O (io), T15 N/C, T16 N/C

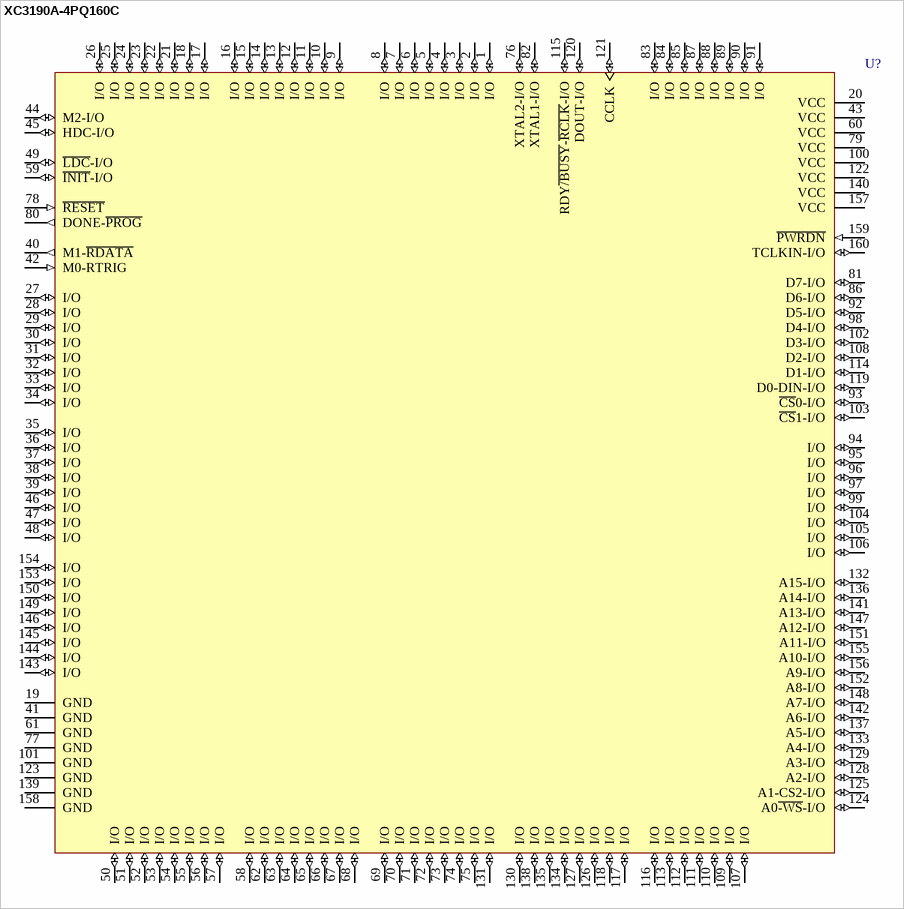
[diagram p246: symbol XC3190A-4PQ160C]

## XC3190A-4PQ160C
designator U?
Logic Cell Array with 320 CLBs, with 138 I/O Pins, 160-Pin PQFP, Commercial Grade; ComponentAvailability: Not for New Design
footprint PQ160_N (QFP, 160-Leads, Body 28 x 28mm, Pitch 0.65mm, IPC Medium Density)
footprint PQ160_L (QFP, 160-Leads, Body 28 x 28mm, Pitch 0.65mm, IPC High Density)
footprint PQ160_M (QFP, 160-Leads, Body 28 x 28mm, Pitch 0.65mm, IPC Low Density)
3D model XC3190A-PQ160 (160-Pin Plastic Quad Flat Pack (PQ160))
pins: 1 I/O (io), 2 I/O (io), 3 I/O (io), 4 I/O (io), 5 I/O (io), 6 I/O (io), 7 I/O (io), 8 I/O (io), 9 I/O (io), 10 I/O (io), 11 I/O (io), 12 I/O (io), 13 I/O (io), 14 I/O (io), 15 I/O (io), 16 I/O (io), 17 I/O (io), 18 I/O (io), 19 GND (power), 20 VCC (power), 21 I/O (io), 22 I/O (io), 23 I/O (io), 24 I/O (io), 25 I/O (io), 26 I/O (io), 27 I/O (io), 28 I/O (io), 29 I/O (io), 30 I/O (io), 31 I/O (io), 32 I/O (io), 33 I/O (io), 34 I/O (io), 35 I/O (io), 36 I/O (io), 37 I/O (io), 38 I/O (io), 39 I/O (io), 40 M1-~{RDATA} (out), 41 GND (power), 42 M0-RTRIG (in), 43 VCC (power), 44 M2-I/O (io), 45 HDC-I/O (io), 46 I/O (io), 47 I/O (io), 48 I/O (io), 49 ~{LDC}-I/O (io), 50 I/O (io), 51 I/O (io), 52 I/O (io), 53 I/O (io), 54 I/O (io), 55 I/O (io), 56 I/O (io), 57 I/O (io), 58 I/O (io), 59 ~{INIT}-I/O (io), 60 VCC (power), 61 GND (power), 62 I/O (io), 63 I/O (io), 64 I/O (io), 65 I/O (io), 66 I/O (io), 67 I/O (io), 68 I/O (io), 69 I/O (io), 70 I/O (io), 71 I/O (io), 72 I/O (io), 73 I/O (io), 74 I/O (io), 75 I/O (io), 76 XTAL2-I/O (io), 77 GND (power), 78 ~{RESET} (in), 79 VCC (power), 80 DONE-~{PROG} (out), 81 D7-I/O (io), 82 XTAL1-I/O (io), 83 I/O (io), 84 I/O (io), 85 I/O (io), 86 D6-I/O (io), 87 I/O (io), 88 I/O (io), 89 I/O (io), 90 I/O (io), 91 I/O (io), 92 D5-I/O (io), 93 ~{CS}0-I/O (io), 94 I/O (io), 95 I/O (io), 96 I/O (io), 97 I/O (io), 98 D4-I/O (io), 99 I/O (io), 100 VCC (power), 101 GND (power), 102 D3-I/O (io), 103 ~{CS}1-I/O (io), 104 I/O (io), 105 I/O (io), 106 I/O (io), 107 I/O (io), 108 D2-I/O (io), 109 I/O (io), 110 I/O (io), 111 I/O (io), 112 I/O (io), 113 I/O (io), 114 D1-I/O (io), 115 RDY~{/BUSY}-~{RCLK}-I/O (io), 116 I/O (io), 117 I/O (io), 118 I/O (io), 119 D0-DIN-I/O (io), 120 DOUT-I/O (io), 121 CCLK (io), 122 VCC (power), 123 GND (power), 124 A0~{-WS}-I/O (io), 125 A1-CS2-I/O (io), 126 I/O (io), 127 I/O (io), 128 A2-I/O (io), 129 A3-I/O (io), 130 I/O (io), 131 I/O (io), 132 A15-I/O (io), 133 A4-I/O (io), 134 I/O (io), 135 I/O (io), 136 A14-I/O (io), 137 A5-I/O (io), 138 I/O (io), 139 GND (power), 140 VCC (power), 141 A13-I/O (io), 142 A6-I/O (io), 143 I/O (io), 144 I/O (io), 145 I/O (io), 146 I/O (io), 147 A12-I/O (io), 148 A7-I/O (io), 149 I/O (io), 150 I/O (io), 151 A11-I/O (io), 152 A8-I/O (io), 153 I/O (io), 154 I/O (io), 155 A10-I/O (io), 156 A9-I/O (io), 157 VCC (power), 158 GND (power), 159 ~{PWRDN} (in), 160 TCLKIN-I/O (io)

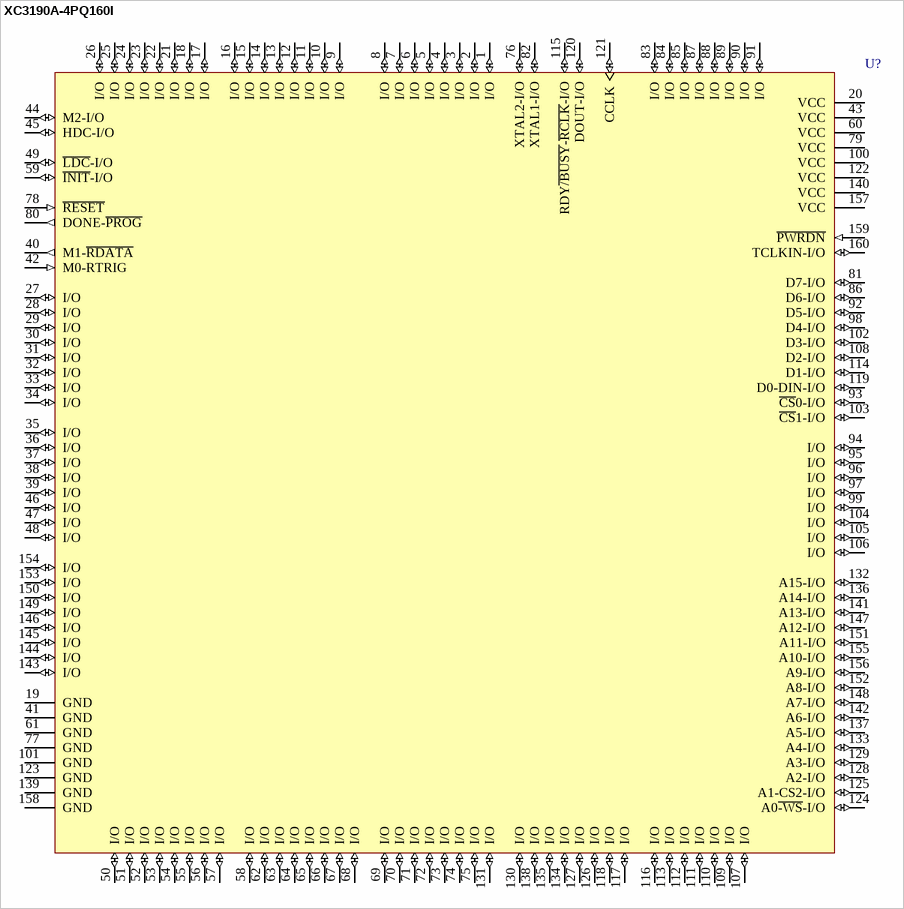
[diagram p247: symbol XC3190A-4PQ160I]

## XC3190A-4PQ160I
designator U?
Logic Cell Array with 320 CLBs, with 138 I/O Pins, 160-Pin PQFP, Industrial Grade; ComponentAvailability: Not for New Design
footprint PQ160_N (QFP, 160-Leads, Body 28 x 28mm, Pitch 0.65mm, IPC Medium Density)
footprint PQ160_L (QFP, 160-Leads, Body 28 x 28mm, Pitch 0.65mm, IPC High Density)
footprint PQ160_M (QFP, 160-Leads, Body 28 x 28mm, Pitch 0.65mm, IPC Low Density)
3D model XC3190A-PQ160 (160-Pin Plastic Quad Flat Pack (PQ160))
pins: 1 I/O (io), 2 I/O (io), 3 I/O (io), 4 I/O (io), 5 I/O (io), 6 I/O (io), 7 I/O (io), 8 I/O (io), 9 I/O (io), 10 I/O (io), 11 I/O (io), 12 I/O (io), 13 I/O (io), 14 I/O (io), 15 I/O (io), 16 I/O (io), 17 I/O (io), 18 I/O (io), 19 GND (power), 20 VCC (power), 21 I/O (io), 22 I/O (io), 23 I/O (io), 24 I/O (io), 25 I/O (io), 26 I/O (io), 27 I/O (io), 28 I/O (io), 29 I/O (io), 30 I/O (io), 31 I/O (io), 32 I/O (io), 33 I/O (io), 34 I/O (io), 35 I/O (io), 36 I/O (io), 37 I/O (io), 38 I/O (io), 39 I/O (io), 40 M1-~{RDATA} (out), 41 GND (power), 42 M0-RTRIG (in), 43 VCC (power), 44 M2-I/O (io), 45 HDC-I/O (io), 46 I/O (io), 47 I/O (io), 48 I/O (io), 49 ~{LDC}-I/O (io), 50 I/O (io), 51 I/O (io), 52 I/O (io), 53 I/O (io), 54 I/O (io), 55 I/O (io), 56 I/O (io), 57 I/O (io), 58 I/O (io), 59 ~{INIT}-I/O (io), 60 VCC (power), 61 GND (power), 62 I/O (io), 63 I/O (io), 64 I/O (io), 65 I/O (io), 66 I/O (io), 67 I/O (io), 68 I/O (io), 69 I/O (io), 70 I/O (io), 71 I/O (io), 72 I/O (io), 73 I/O (io), 74 I/O (io), 75 I/O (io), 76 XTAL2-I/O (io), 77 GND (power), 78 ~{RESET} (in), 79 VCC (power), 80 DONE-~{PROG} (out), 81 D7-I/O (io), 82 XTAL1-I/O (io), 83 I/O (io), 84 I/O (io), 85 I/O (io), 86 D6-I/O (io), 87 I/O (io), 88 I/O (io), 89 I/O (io), 90 I/O (io), 91 I/O (io), 92 D5-I/O (io), 93 ~{CS}0-I/O (io), 94 I/O (io), 95 I/O (io), 96 I/O (io), 97 I/O (io), 98 D4-I/O (io), 99 I/O (io), 100 VCC (power), 101 GND (power), 102 D3-I/O (io), 103 ~{CS}1-I/O (io), 104 I/O (io), 105 I/O (io), 106 I/O (io), 107 I/O (io), 108 D2-I/O (io), 109 I/O (io), 110 I/O (io), 111 I/O (io), 112 I/O (io), 113 I/O (io), 114 D1-I/O (io), 115 RDY~{/BUSY}-~{RCLK}-I/O (io), 116 I/O (io), 117 I/O (io), 118 I/O (io), 119 D0-DIN-I/O (io), 120 DOUT-I/O (io), 121 CCLK (io), 122 VCC (power), 123 GND (power), 124 A0~{-WS}-I/O (io), 125 A1-CS2-I/O (io), 126 I/O (io), 127 I/O (io), 128 A2-I/O (io), 129 A3-I/O (io), 130 I/O (io), 131 I/O (io), 132 A15-I/O (io), 133 A4-I/O (io), 134 I/O (io), 135 I/O (io), 136 A14-I/O (io), 137 A5-I/O (io), 138 I/O (io), 139 GND (power), 140 VCC (power), 141 A13-I/O (io), 142 A6-I/O (io), 143 I/O (io), 144 I/O (io), 145 I/O (io), 146 I/O (io), 147 A12-I/O (io), 148 A7-I/O (io), 149 I/O (io), 150 I/O (io), 151 A11-I/O (io), 152 A8-I/O (io), 153 I/O (io), 154 I/O (io), 155 A10-I/O (io), 156 A9-I/O (io), 157 VCC (power), 158 GND (power), 159 ~{PWRDN} (in), 160 TCLKIN-I/O (io)

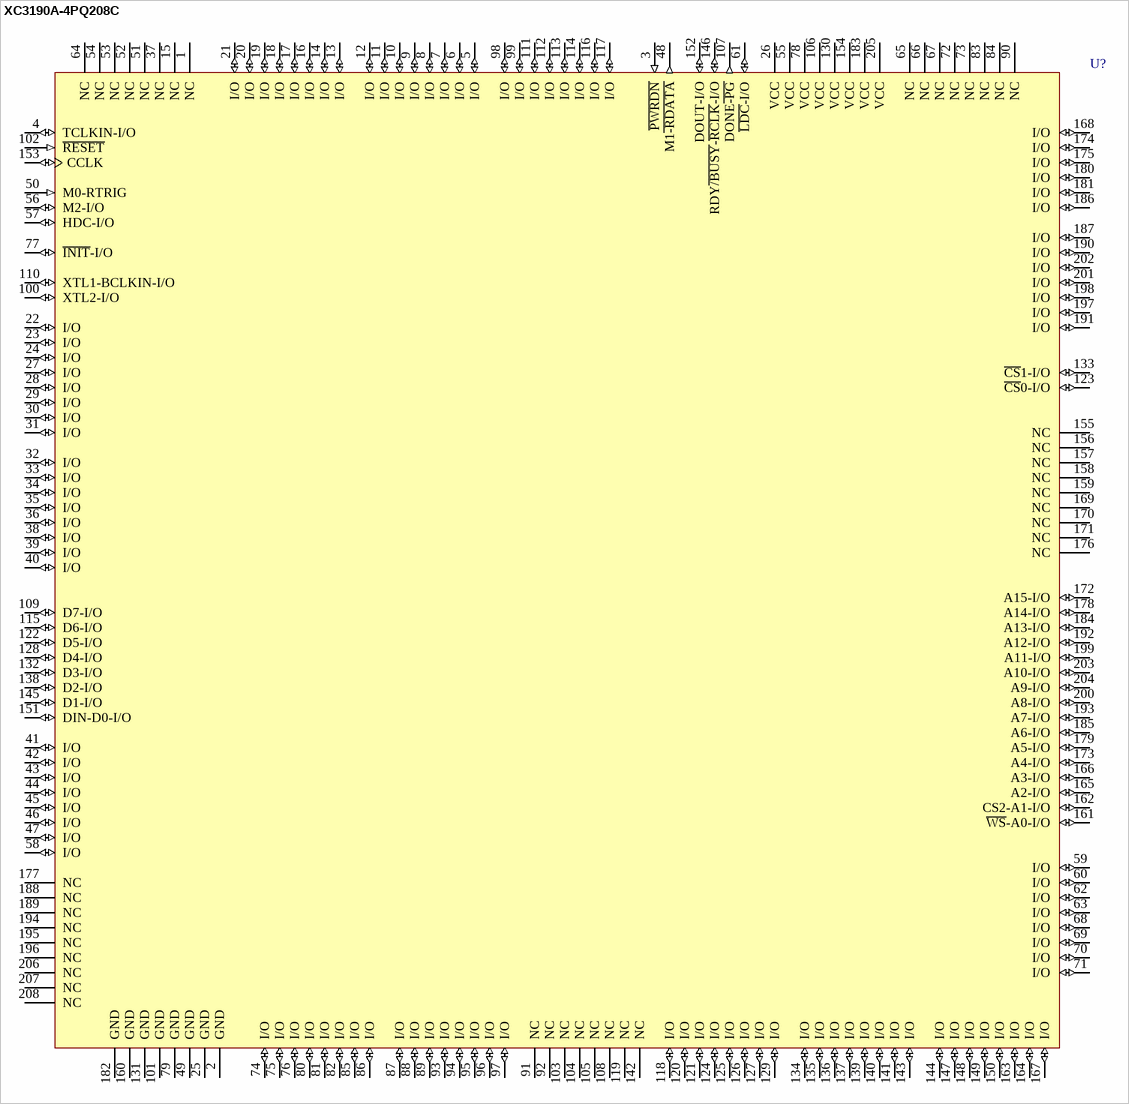
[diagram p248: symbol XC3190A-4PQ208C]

## XC3190A-4PQ208C
designator U?
Logic Cell Array with 320 CLBs, with 144 I/O Pins, 208-Pin PQFP, Commercial Grade; ComponentAvailability: Not for New Design
footprint PQ208_N (Shrink QFP, 208-Leads, Body 28x28mm, Pitch 0.5mm, IPC Medium Density)
footprint PQ208_L (Shrink QFP, 208-Leads, Body 28x28mm, Pitch 0.5mm, IPC High Density)
footprint PQ208_M (Shrink QFP, 208-Leads, Body 28x28mm, Pitch 0.5mm, IPC Low Density)
3D model XC3190A-PQ208 (208-Pin Plastic Quad Flat Pack (PQ208))
pins: 1 NC, 2 GND (power), 3 ~{PWRDN} (in), 4 TCLKIN-I/O (io), 5 I/O (io), 6 I/O (io), 7 I/O (io), 8 I/O (io), 9 I/O (io), 10 I/O (io), 11 I/O (io), 12 I/O (io), 13 I/O (io), 14 I/O (io), 15 NC, 16 I/O (io), 17 I/O (io), 18 I/O (io), 19 I/O (io), 20 I/O (io), 21 I/O (io), 22 I/O (io), 23 I/O (io), 24 I/O (io), 25 GND (power), 26 VCC (power), 27 I/O (io), 28 I/O (io), 29 I/O (io), 30 I/O (io), 31 I/O (io), 32 I/O (io), 33 I/O (io), 34 I/O (io), 35 I/O (io), 36 I/O (io), 37 NC, 38 I/O (io), 39 I/O (io), 40 I/O (io), 41 I/O (io), 42 I/O (io), 43 I/O (io), 44 I/O (io), 45 I/O (io), 46 I/O (io), 47 I/O (io), 48 M1~{-RDATA} (out), 49 GND (power), 50 M0-RTRIG (in), 51 NC, 52 NC, 53 NC, 54 NC, 55 VCC (power), 56 M2-I/O (io), 57 HDC-I/O (io), 58 I/O (io), 59 I/O (io), 60 I/O (io), 61 ~{LDC}-I/O (io), 62 I/O (io), 63 I/O (io), 64 NC, 65 NC, 66 NC, 67 NC, 68 I/O (io), 69 I/O (io), 70 I/O (io), 71 I/O (io), 72 NC, 73 NC, 74 I/O (io), 75 I/O (io), 76 I/O (io), 77 ~{INIT}-I/O (io), 78 VCC (power), 79 GND (power), 80 I/O (io), 81 I/O (io), 82 I/O (io), 83 NC, 84 NC, 85 I/O (io), 86 I/O (io), 87 I/O (io), 88 I/O (io), 89 I/O (io), 90 NC, 91 NC, 92 NC, 93 I/O (io), 94 I/O (io), 95 I/O (io), 96 I/O (io), 97 I/O (io), 98 I/O (io), 99 I/O (io), 100 XTL2-I/O (io), 101 GND (power), 102 ~{RESET} (in), 103 NC, 104 NC, 105 NC, 106 VCC (power), 107 DONE~{-PG} (out), 108 NC, 109 D7-I/O (io), 110 XTL1-BCLKIN-I/O (io), 111 I/O (io), 112 I/O (io), 113 I/O (io), 114 I/O (io), 115 D6-I/O (io), 116 I/O (io), 117 I/O (io), 118 I/O (io), 119 NC, 120 I/O (io), 121 I/O (io), 122 D5-I/O (io), 123 ~{CS}0-I/O (io), 124 I/O (io), 125 I/O (io), 126 I/O (io), 127 I/O (io), 128 D4-I/O (io), 129 I/O (io), 130 VCC (power), 131 GND (power), 132 D3-I/O (io), 133 ~{CS}1-I/O (io), 134 I/O (io), 135 I/O (io), 136 I/O (io), 137 I/O (io), 138 D2-I/O (io), 139 I/O (io), 140 I/O (io), 141 I/O (io), 142 NC, 143 I/O (io), 144 I/O (io), 145 D1-I/O (io), 146 RDY~{/BUSY}-~{RCLK}-I/O (io), 147 I/O (io), 148 I/O (io), 149 I/O (io), 150 I/O (io), 151 DIN-D0-I/O (io), 152 DOUT-I/O (io), 153 CCLK (io), 154 VCC (power), 155 NC, 156 NC, 157 NC, 158 NC, 159 NC, 160 GND (power), 161 ~{WS}-A0-I/O (io), 162 CS2-A1-I/O (io), 163 I/O (io), 164 I/O (io), 165 A2-I/O (io), 166 A3-I/O (io), 167 I/O (io), 168 I/O (io), 169 NC, 170 NC, 171 NC, 172 A15-I/O (io), 173 A4-I/O (io), 174 I/O (io), 175 I/O (io), 176 NC, 177 NC, 178 A14-I/O (io), 179 A5-I/O (io), 180 I/O (io), 181 I/O (io), 182 GND (power), 183 VCC (power), 184 A13-I/O (io), 185 A6-I/O (io), 186 I/O (io), 187 I/O (io), 188 NC, 189 NC, 190 I/O (io), 191 I/O (io), 192 A12-I/O (io), 193 A7-I/O (io), 194 NC, 195 NC, 196 NC, 197 I/O (io), 198 I/O (io), 199 A11-I/O (io), 200 A8-I/O (io), 201 I/O (io), 202 I/O (io), 203 A10-I/O (io), 204 A9-I/O (io), 205 VCC (power), 206 NC, 207 NC, 208 NC

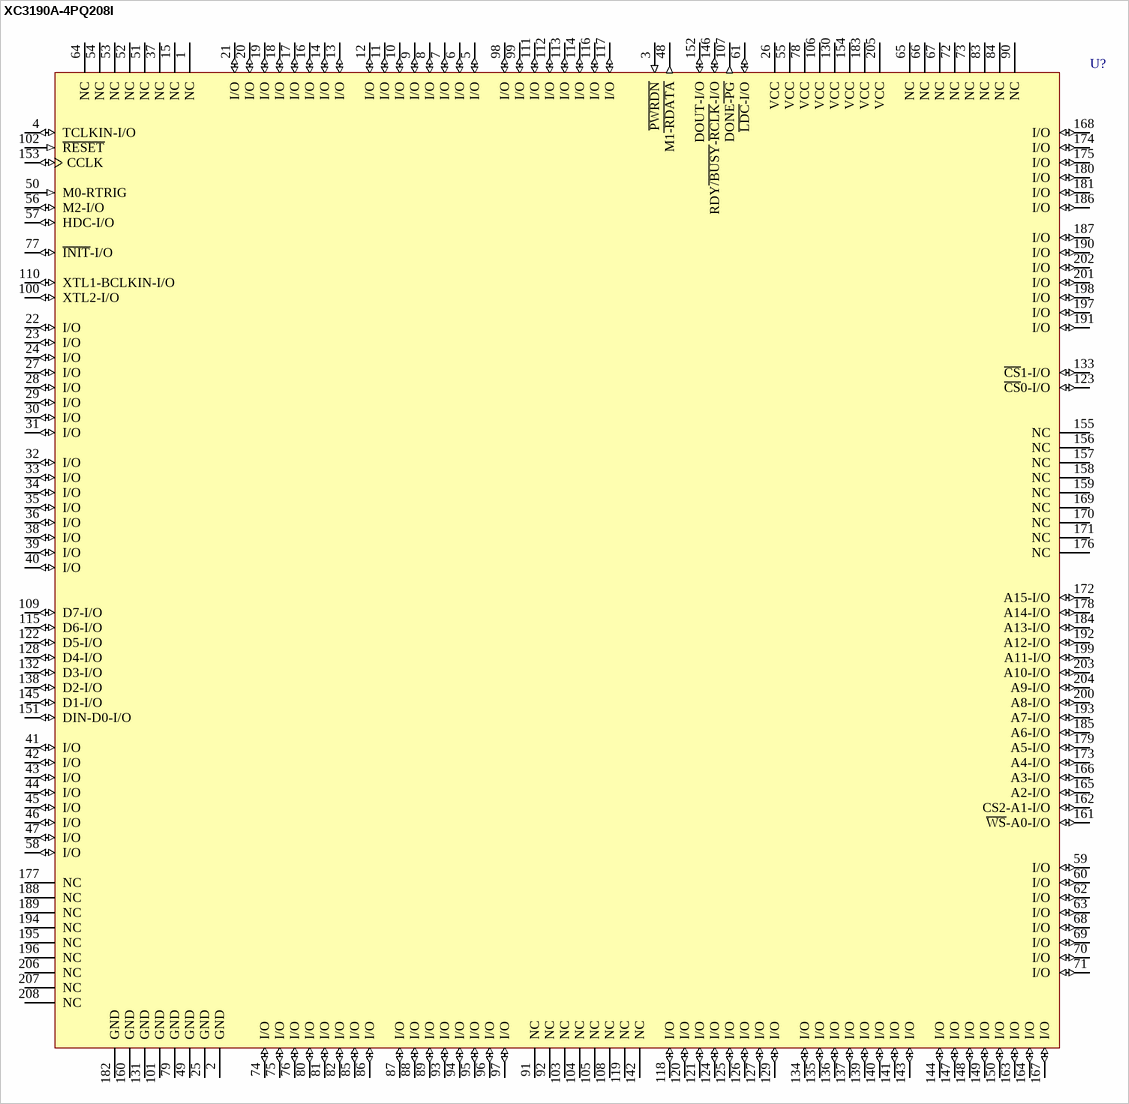
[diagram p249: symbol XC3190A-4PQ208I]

## XC3190A-4PQ208I
designator U?
Logic Cell Array with 320 CLBs, with 144 I/O Pins, 208-Pin PQFP, Industrial Grade; ComponentAvailability: Not for New Design
footprint PQ208_N (Shrink QFP, 208-Leads, Body 28x28mm, Pitch 0.5mm, IPC Medium Density)
footprint PQ208_L (Shrink QFP, 208-Leads, Body 28x28mm, Pitch 0.5mm, IPC High Density)
footprint PQ208_M (Shrink QFP, 208-Leads, Body 28x28mm, Pitch 0.5mm, IPC Low Density)
3D model XC3190A-PQ208 (208-Pin Plastic Quad Flat Pack (PQ208))
pins: 1 NC, 2 GND (power), 3 ~{PWRDN} (in), 4 TCLKIN-I/O (io), 5 I/O (io), 6 I/O (io), 7 I/O (io), 8 I/O (io), 9 I/O (io), 10 I/O (io), 11 I/O (io), 12 I/O (io), 13 I/O (io), 14 I/O (io), 15 NC, 16 I/O (io), 17 I/O (io), 18 I/O (io), 19 I/O (io), 20 I/O (io), 21 I/O (io), 22 I/O (io), 23 I/O (io), 24 I/O (io), 25 GND (power), 26 VCC (power), 27 I/O (io), 28 I/O (io), 29 I/O (io), 30 I/O (io), 31 I/O (io), 32 I/O (io), 33 I/O (io), 34 I/O (io), 35 I/O (io), 36 I/O (io), 37 NC, 38 I/O (io), 39 I/O (io), 40 I/O (io), 41 I/O (io), 42 I/O (io), 43 I/O (io), 44 I/O (io), 45 I/O (io), 46 I/O (io), 47 I/O (io), 48 M1~{-RDATA} (out), 49 GND (power), 50 M0-RTRIG (in), 51 NC, 52 NC, 53 NC, 54 NC, 55 VCC (power), 56 M2-I/O (io), 57 HDC-I/O (io), 58 I/O (io), 59 I/O (io), 60 I/O (io), 61 ~{LDC}-I/O (io), 62 I/O (io), 63 I/O (io), 64 NC, 65 NC, 66 NC, 67 NC, 68 I/O (io), 69 I/O (io), 70 I/O (io), 71 I/O (io), 72 NC, 73 NC, 74 I/O (io), 75 I/O (io), 76 I/O (io), 77 ~{INIT}-I/O (io), 78 VCC (power), 79 GND (power), 80 I/O (io), 81 I/O (io), 82 I/O (io), 83 NC, 84 NC, 85 I/O (io), 86 I/O (io), 87 I/O (io), 88 I/O (io), 89 I/O (io), 90 NC, 91 NC, 92 NC, 93 I/O (io), 94 I/O (io), 95 I/O (io), 96 I/O (io), 97 I/O (io), 98 I/O (io), 99 I/O (io), 100 XTL2-I/O (io), 101 GND (power), 102 ~{RESET} (in), 103 NC, 104 NC, 105 NC, 106 VCC (power), 107 DONE~{-PG} (out), 108 NC, 109 D7-I/O (io), 110 XTL1-BCLKIN-I/O (io), 111 I/O (io), 112 I/O (io), 113 I/O (io), 114 I/O (io), 115 D6-I/O (io), 116 I/O (io), 117 I/O (io), 118 I/O (io), 119 NC, 120 I/O (io), 121 I/O (io), 122 D5-I/O (io), 123 ~{CS}0-I/O (io), 124 I/O (io), 125 I/O (io), 126 I/O (io), 127 I/O (io), 128 D4-I/O (io), 129 I/O (io), 130 VCC (power), 131 GND (power), 132 D3-I/O (io), 133 ~{CS}1-I/O (io), 134 I/O (io), 135 I/O (io), 136 I/O (io), 137 I/O (io), 138 D2-I/O (io), 139 I/O (io), 140 I/O (io), 141 I/O (io), 142 NC, 143 I/O (io), 144 I/O (io), 145 D1-I/O (io), 146 RDY~{/BUSY}-~{RCLK}-I/O (io), 147 I/O (io), 148 I/O (io), 149 I/O (io), 150 I/O (io), 151 DIN-D0-I/O (io), 152 DOUT-I/O (io), 153 CCLK (io), 154 VCC (power), 155 NC, 156 NC, 157 NC, 158 NC, 159 NC, 160 GND (power), 161 ~{WS}-A0-I/O (io), 162 CS2-A1-I/O (io), 163 I/O (io), 164 I/O (io), 165 A2-I/O (io), 166 A3-I/O (io), 167 I/O (io), 168 I/O (io), 169 NC, 170 NC, 171 NC, 172 A15-I/O (io), 173 A4-I/O (io), 174 I/O (io), 175 I/O (io), 176 NC, 177 NC, 178 A14-I/O (io), 179 A5-I/O (io), 180 I/O (io), 181 I/O (io), 182 GND (power), 183 VCC (power), 184 A13-I/O (io), 185 A6-I/O (io), 186 I/O (io), 187 I/O (io), 188 NC, 189 NC, 190 I/O (io), 191 I/O (io), 192 A12-I/O (io), 193 A7-I/O (io), 194 NC, 195 NC, 196 NC, 197 I/O (io), 198 I/O (io), 199 A11-I/O (io), 200 A8-I/O (io), 201 I/O (io), 202 I/O (io), 203 A10-I/O (io), 204 A9-I/O (io), 205 VCC (power), 206 NC, 207 NC, 208 NC

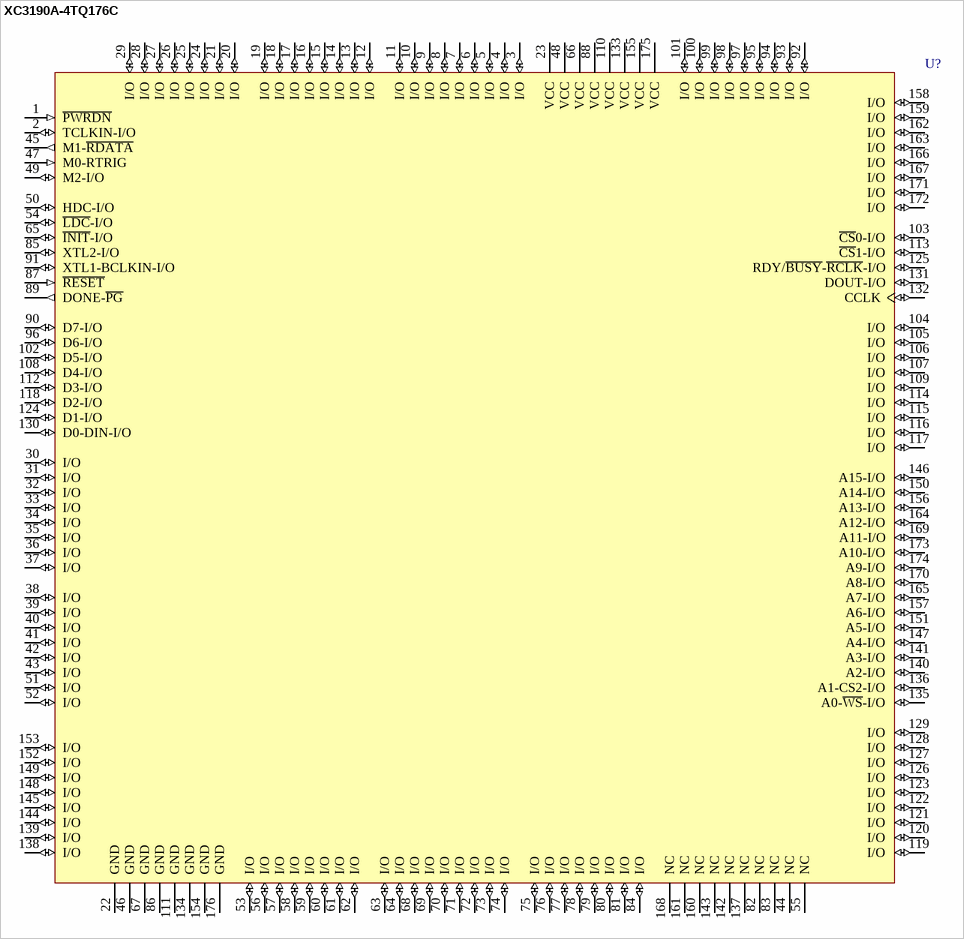
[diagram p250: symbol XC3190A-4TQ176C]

## XC3190A-4TQ176C
designator U?
Logic Cell Array with 320 CLBs, with 144 I/O Pins, 176-Pin TQFP, Commercial Grade; ComponentAvailability: Not for New Design
footprint TQ176_N (Thin QFP, 176-Leads, Body 24x24mm, Pitch 0.5mm, IPC Medium Density)
footprint TQ176_L (Thin QFP, 176-Leads, Body 24x24mm, Pitch 0.5mm, IPC High Density)
footprint TQ176_M (Thin QFP, 176-Leads, Body 24x24mm, Pitch 0.5mm, IPC Low Density)
3D model XC3190A-TQ176 (176-Pin Thin Quad Flat Pack (TQ176))
pins: 1 ~{PWRDN} (in), 2 TCLKIN-I/O (io), 3 I/O (io), 4 I/O (io), 5 I/O (io), 6 I/O (io), 7 I/O (io), 8 I/O (io), 9 I/O (io), 10 I/O (io), 11 I/O (io), 12 I/O (io), 13 I/O (io), 14 I/O (io), 15 I/O (io), 16 I/O (io), 17 I/O (io), 18 I/O (io), 19 I/O (io), 20 I/O (io), 21 I/O (io), 22 GND (power), 23 VCC (power), 24 I/O (io), 25 I/O (io), 26 I/O (io), 27 I/O (io), 28 I/O (io), 29 I/O (io), 30 I/O (io), 31 I/O (io), 32 I/O (io), 33 I/O (io), 34 I/O (io), 35 I/O (io), 36 I/O (io), 37 I/O (io), 38 I/O (io), 39 I/O (io), 40 I/O (io), 41 I/O (io), 42 I/O (io), 43 I/O (io), 44 NC, 45 M1-~{RDATA} (out), 46 GND (power), 47 M0-RTRIG (in), 48 VCC (power), 49 M2-I/O (io), 50 HDC-I/O (io), 51 I/O (io), 52 I/O (io), 53 I/O (io), 54 ~{LDC}-I/O (io), 55 NC, 56 I/O (io), 57 I/O (io), 58 I/O (io), 59 I/O (io), 60 I/O (io), 61 I/O (io), 62 I/O (io), 63 I/O (io), 64 I/O (io), 65 ~{INIT}-I/O (io), 66 VCC (power), 67 GND (power), 68 I/O (io), 69 I/O (io), 70 I/O (io), 71 I/O (io), 72 I/O (io), 73 I/O (io), 74 I/O (io), 75 I/O (io), 76 I/O (io), 77 I/O (io), 78 I/O (io), 79 I/O (io), 80 I/O (io), 81 I/O (io), 82 NC, 83 NC, 84 I/O (io), 85 XTL2-I/O (io), 86 GND (power), 87 ~{RESET} (in), 88 VCC (power), 89 DONE-~{PG} (out), 90 D7-I/O (io), 91 XTL1-BCLKIN-I/O (io), 92 I/O (io), 93 I/O (io), 94 I/O (io), 95 I/O (io), 96 D6-I/O (io), 97 I/O (io), 98 I/O (io), 99 I/O (io), 100 I/O (io), 101 I/O (io), 102 D5-I/O (io), 103 ~{CS}0-I/O (io), 104 I/O (io), 105 I/O (io), 106 I/O (io), 107 I/O (io), 108 D4-I/O (io), 109 I/O (io), 110 VCC (power), 111 GND (power), 112 D3-I/O (io), 113 ~{CS}1-I/O (io), 114 I/O (io), 115 I/O (io), 116 I/O (io), 117 I/O (io), 118 D2-I/O (io), 119 I/O (io), 120 I/O (io), 121 I/O (io), 122 I/O (io), 123 I/O (io), 124 D1-I/O (io), 125 RDY/~{BUSY}-~{RCLK}-I/O (io), 126 I/O (io), 127 I/O (io), 128 I/O (io), 129 I/O (io), 130 D0-DIN-I/O (io), 131 DOUT-I/O (io), 132 CCLK (io), 133 VCC (power), 134 GND (power), 135 A0-~{WS}-I/O (io), 136 A1-CS2-I/O (io), 137 NC, 138 I/O (io), 139 I/O (io), 140 A2-I/O (io), 141 A3-I/O (io), 142 NC, 143 NC, 144 I/O (io), 145 I/O (io), 146 A15-I/O (io), 147 A4-I/O (io), 148 I/O (io), 149 I/O (io), 150 A14-I/O (io), 151 A5-I/O (io), 152 I/O (io), 153 I/O (io), 154 GND (power), 155 VCC (power), 156 A13-I/O (io), 157 A6-I/O (io), 158 I/O (io), 159 I/O (io), 160 NC, 161 NC, 162 I/O (io), 163 I/O (io), 164 A12-I/O (io), 165 A7-I/O (io), 166 I/O (io), 167 I/O (io), 168 NC, 169 A11-I/O (io), 170 A8-I/O (io), 171 I/O (io), 172 I/O (io), 173 A10-I/O (io), 174 A9-I/O (io), 175 VCC (power), 176 GND (power)

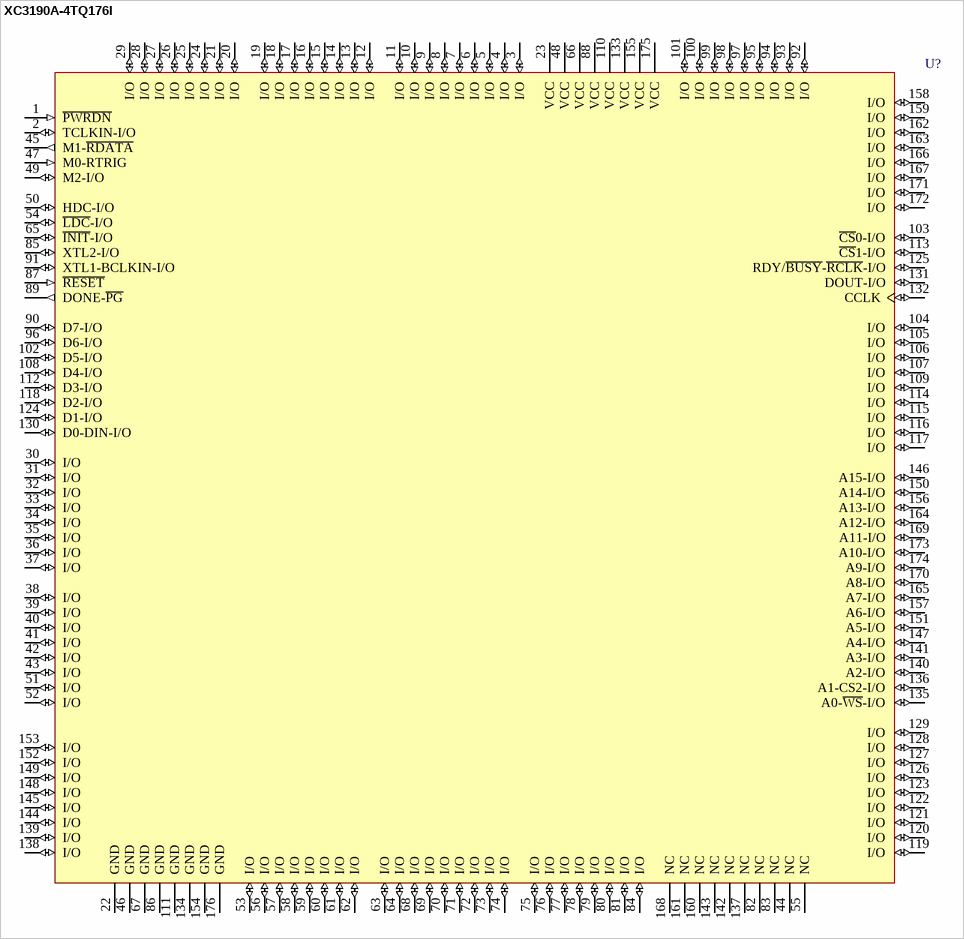
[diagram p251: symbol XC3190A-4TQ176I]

## XC3190A-4TQ176I
designator U?
Logic Cell Array with 320 CLBs, with 144 I/O Pins, 176-Pin TQFP, Industrial Grade; ComponentAvailability: Not for New Design
footprint TQ176_N (Thin QFP, 176-Leads, Body 24x24mm, Pitch 0.5mm, IPC Medium Density)
footprint TQ176_L (Thin QFP, 176-Leads, Body 24x24mm, Pitch 0.5mm, IPC High Density)
footprint TQ176_M (Thin QFP, 176-Leads, Body 24x24mm, Pitch 0.5mm, IPC Low Density)
3D model XC3190A-TQ176 (176-Pin Thin Quad Flat Pack (TQ176))
pins: 1 ~{PWRDN} (in), 2 TCLKIN-I/O (io), 3 I/O (io), 4 I/O (io), 5 I/O (io), 6 I/O (io), 7 I/O (io), 8 I/O (io), 9 I/O (io), 10 I/O (io), 11 I/O (io), 12 I/O (io), 13 I/O (io), 14 I/O (io), 15 I/O (io), 16 I/O (io), 17 I/O (io), 18 I/O (io), 19 I/O (io), 20 I/O (io), 21 I/O (io), 22 GND (power), 23 VCC (power), 24 I/O (io), 25 I/O (io), 26 I/O (io), 27 I/O (io), 28 I/O (io), 29 I/O (io), 30 I/O (io), 31 I/O (io), 32 I/O (io), 33 I/O (io), 34 I/O (io), 35 I/O (io), 36 I/O (io), 37 I/O (io), 38 I/O (io), 39 I/O (io), 40 I/O (io), 41 I/O (io), 42 I/O (io), 43 I/O (io), 44 NC, 45 M1-~{RDATA} (out), 46 GND (power), 47 M0-RTRIG (in), 48 VCC (power), 49 M2-I/O (io), 50 HDC-I/O (io), 51 I/O (io), 52 I/O (io), 53 I/O (io), 54 ~{LDC}-I/O (io), 55 NC, 56 I/O (io), 57 I/O (io), 58 I/O (io), 59 I/O (io), 60 I/O (io), 61 I/O (io), 62 I/O (io), 63 I/O (io), 64 I/O (io), 65 ~{INIT}-I/O (io), 66 VCC (power), 67 GND (power), 68 I/O (io), 69 I/O (io), 70 I/O (io), 71 I/O (io), 72 I/O (io), 73 I/O (io), 74 I/O (io), 75 I/O (io), 76 I/O (io), 77 I/O (io), 78 I/O (io), 79 I/O (io), 80 I/O (io), 81 I/O (io), 82 NC, 83 NC, 84 I/O (io), 85 XTL2-I/O (io), 86 GND (power), 87 ~{RESET} (in), 88 VCC (power), 89 DONE-~{PG} (out), 90 D7-I/O (io), 91 XTL1-BCLKIN-I/O (io), 92 I/O (io), 93 I/O (io), 94 I/O (io), 95 I/O (io), 96 D6-I/O (io), 97 I/O (io), 98 I/O (io), 99 I/O (io), 100 I/O (io), 101 I/O (io), 102 D5-I/O (io), 103 ~{CS}0-I/O (io), 104 I/O (io), 105 I/O (io), 106 I/O (io), 107 I/O (io), 108 D4-I/O (io), 109 I/O (io), 110 VCC (power), 111 GND (power), 112 D3-I/O (io), 113 ~{CS}1-I/O (io), 114 I/O (io), 115 I/O (io), 116 I/O (io), 117 I/O (io), 118 D2-I/O (io), 119 I/O (io), 120 I/O (io), 121 I/O (io), 122 I/O (io), 123 I/O (io), 124 D1-I/O (io), 125 RDY/~{BUSY}-~{RCLK}-I/O (io), 126 I/O (io), 127 I/O (io), 128 I/O (io), 129 I/O (io), 130 D0-DIN-I/O (io), 131 DOUT-I/O (io), 132 CCLK (io), 133 VCC (power), 134 GND (power), 135 A0-~{WS}-I/O (io), 136 A1-CS2-I/O (io), 137 NC, 138 I/O (io), 139 I/O (io), 140 A2-I/O (io), 141 A3-I/O (io), 142 NC, 143 NC, 144 I/O (io), 145 I/O (io), 146 A15-I/O (io), 147 A4-I/O (io), 148 I/O (io), 149 I/O (io), 150 A14-I/O (io), 151 A5-I/O (io), 152 I/O (io), 153 I/O (io), 154 GND (power), 155 VCC (power), 156 A13-I/O (io), 157 A6-I/O (io), 158 I/O (io), 159 I/O (io), 160 NC, 161 NC, 162 I/O (io), 163 I/O (io), 164 A12-I/O (io), 165 A7-I/O (io), 166 I/O (io), 167 I/O (io), 168 NC, 169 A11-I/O (io), 170 A8-I/O (io), 171 I/O (io), 172 I/O (io), 173 A10-I/O (io), 174 A9-I/O (io), 175 VCC (power), 176 GND (power)

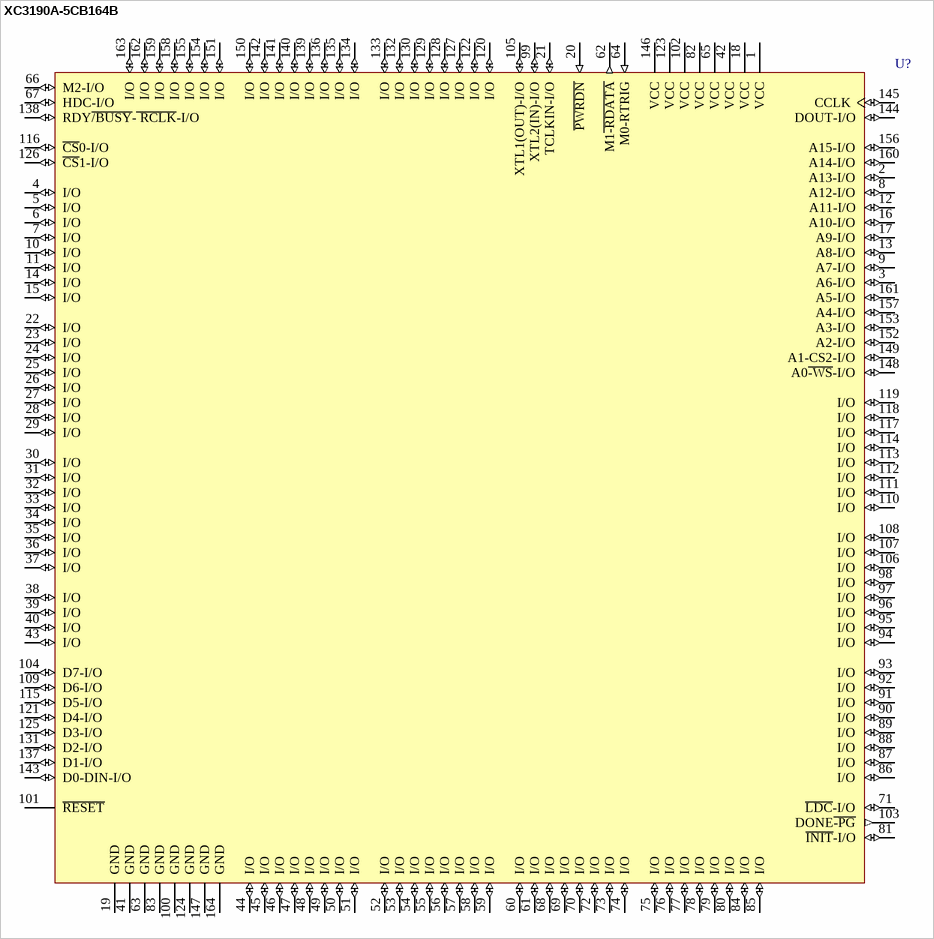
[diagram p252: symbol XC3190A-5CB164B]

## XC3190A-5CB164B
designator U?
Logic Cell Array with 320 CLBs, with 142 I/O Pins, 164-Pin CQFP, Military Class B Grade; ComponentAvailability: Not for New Design
footprint CB164_N (CQFP, 164-Leads, Body 29x29mm; Pitch 0.635mm, Gullwing Leadform, IPC Medium Density)
footprint CB164_L (CQFP, 164-Leads, Body 29x29mm; Pitch 0.635mm, Gullwing Leadform, IPC High Density)
footprint CB164_M (CQFP, 164-Leads, Body 29x29mm; Pitch 0.635mm, Gullwing Leadform, IPC Low Density)
3D model XC3190A-CB164 (164-Pin Ceramic Brazed Quad Flat Pack (CB164))
pins: 1 VCC (power), 2 A13-I/O (io), 3 A6-I/O (io), 4 I/O (io), 5 I/O (io), 6 I/O (io), 7 I/O (io), 8 A12-I/O (io), 9 A7-I/O (io), 10 I/O (io), 11 I/O (io), 12 A11-I/O (io), 13 A8-I/O (io), 14 I/O (io), 15 I/O (io), 16 A10-I/O (io), 17 A9-I/O (io), 18 VCC (power), 19 GND (power), 20 ~{PWRDN} (in), 21 TCLKIN-I/O (io), 22 I/O (io), 23 I/O (io), 24 I/O (io), 25 I/O (io), 26 I/O (io), 27 I/O (io), 28 I/O (io), 29 I/O (io), 30 I/O (io), 31 I/O (io), 32 I/O (io), 33 I/O (io), 34 I/O (io), 35 I/O (io), 36 I/O (io), 37 I/O (io), 38 I/O (io), 39 I/O (io), 40 I/O (io), 41 GND (power), 42 VCC (power), 43 I/O (io), 44 I/O (io), 45 I/O (io), 46 I/O (io), 47 I/O (io), 48 I/O (io), 49 I/O (io), 50 I/O (io), 51 I/O (io), 52 I/O (io), 53 I/O (io), 54 I/O (io), 55 I/O (io), 56 I/O (io), 57 I/O (io), 58 I/O (io), 59 I/O (io), 60 I/O (io), 61 I/O (io), 62 M1~{-RDATA} (out), 63 GND (power), 64 M0-RTRIG (in), 65 VCC (power), 66 M2-I/O (io), 67 HDC-I/O (io), 68 I/O (io), 69 I/O (io), 70 I/O (io), 71 ~{LDC}-I/O (io), 72 I/O (io), 73 I/O (io), 74 I/O (io), 75 I/O (io), 76 I/O (io), 77 I/O (io), 78 I/O (io), 79 I/O (io), 80 I/O (io), 81 ~{INIT}-I/O (io), 82 VCC (power), 83 GND (power), 84 I/O (io), 85 I/O (io), 86 I/O (io), 87 I/O (io), 88 I/O (io), 89 I/O (io), 90 I/O (io), 91 I/O (io), 92 I/O (io), 93 I/O (io), 94 I/O (io), 95 I/O (io), 96 I/O (io), 97 I/O (io), 98 I/O (io), 99 XTL2(IN)-I/O (io), 100 GND (power), 101 ~{RESET} (oe), 102 VCC (power), 103 DONE~{-PG} (out), 104 D7-I/O (io), 105 XTL1(OUT)-I/O (io), 106 I/O (io), 107 I/O (io), 108 I/O (io), 109 D6-I/O (io), 110 I/O (io), 111 I/O (io), 112 I/O (io), 113 I/O (io), 114 I/O (io), 115 D5-I/O (io), 116 ~{CS}0-I/O (io), 117 I/O (io), 118 I/O (io), 119 I/O (io), 120 I/O (io), 121 D4-I/O (io), 122 I/O (io), 123 VCC (power), 124 GND (power), 125 D3-I/O (io), 126 ~{CS}1-I/O (io), 127 I/O (io), 128 I/O (io), 129 I/O (io), 130 I/O (io), 131 D2-I/O (io), 132 I/O (io), 133 I/O (io), 134 I/O (io), 135 I/O (io), 136 I/O (io), 137 D1-I/O (io), 138 RDY~{/BUSY}-~{ RCLK}-I/O (io), 139 I/O (io), 140 I/O (io), 141 I/O (io), 142 I/O (io), 143 D0-DIN-I/O (io), 144 DOUT-I/O (io), 145 CCLK (io), 146 VCC (power), 147 GND (power), 148 A0~{-WS}-I/O (io), 149 A1-CS2-I/O (io), 150 I/O (io), 151 I/O (io), 152 A2-I/O (io), 153 A3-I/O (io), 154 I/O (io), 155 I/O (io), 156 A15-I/O (io), 157 A4-I/O (io), 158 I/O (io), 159 I/O (io), 160 A14-I/O (io), 161 A5-I/O (io), 162 I/O (io), 163 I/O (io), 164 GND (power)

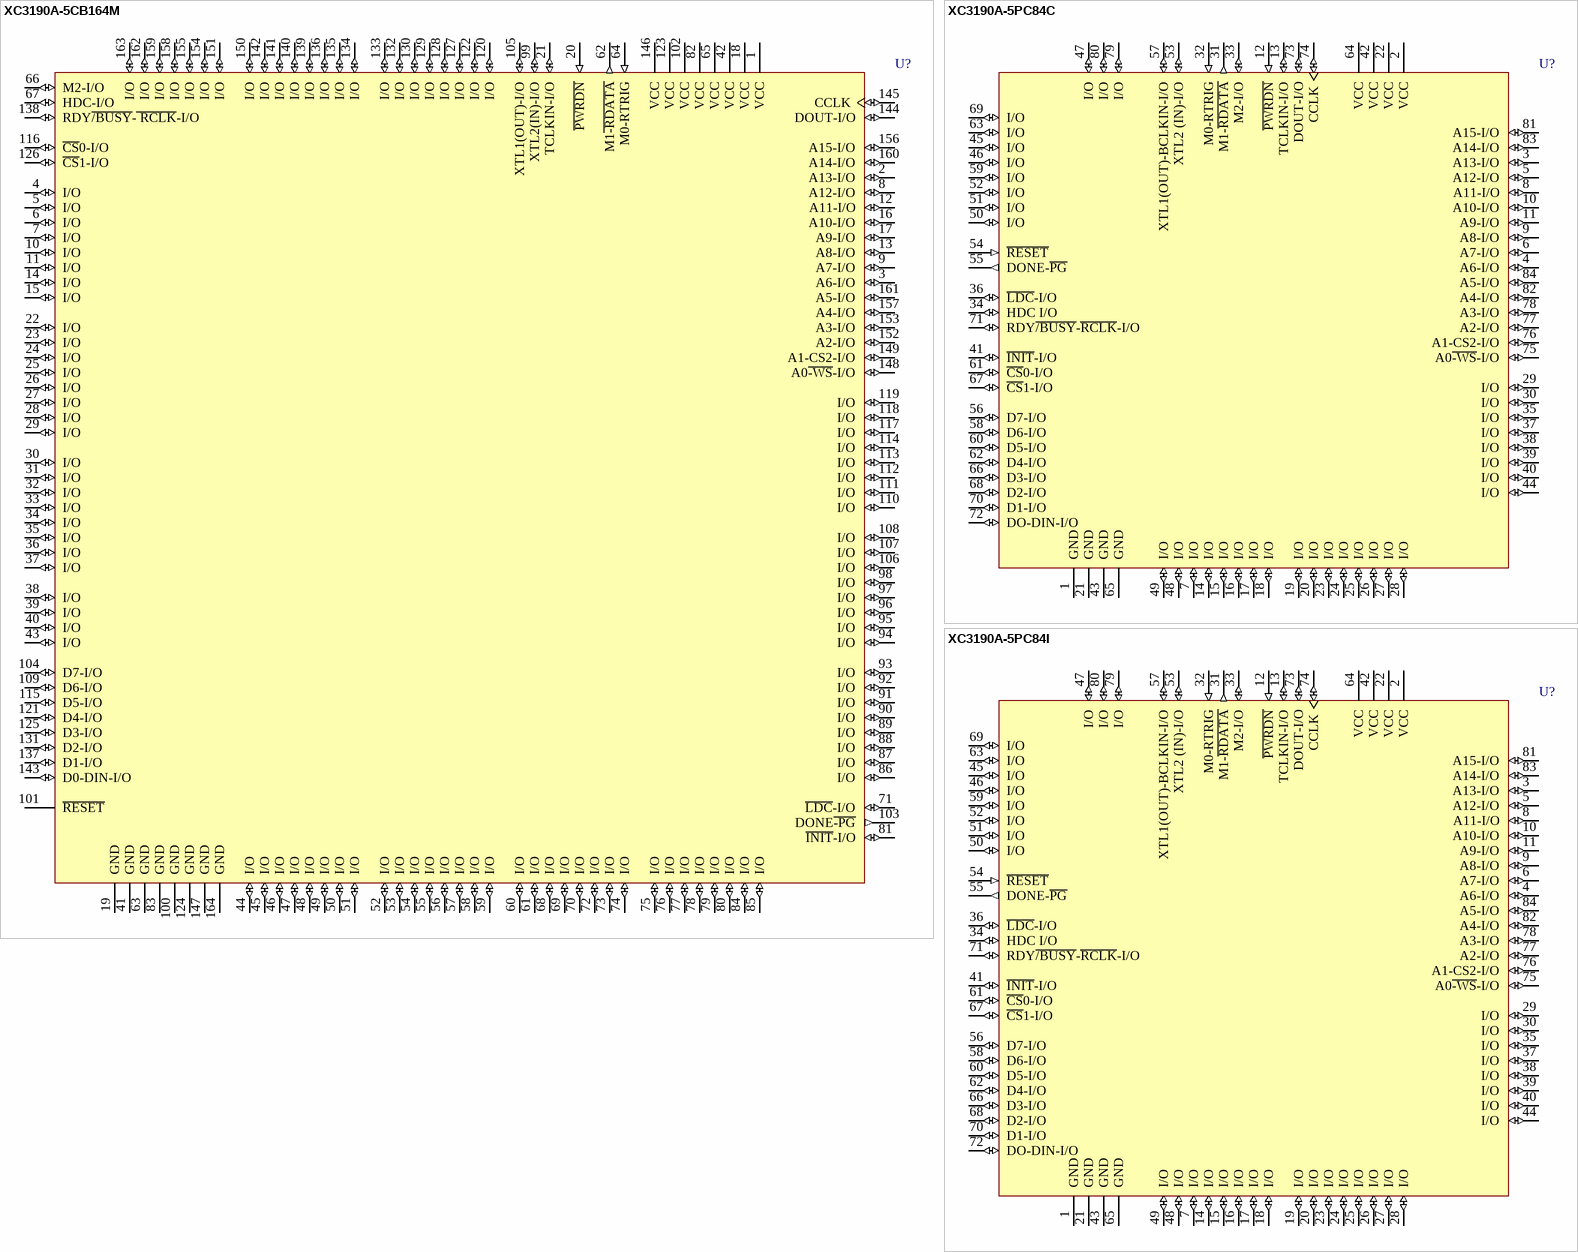
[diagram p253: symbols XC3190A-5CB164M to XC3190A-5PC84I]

## XC3190A-5CB164M
designator U?
Logic Cell Array with 320 CLBs, with 142 I/O Pins, 164-Pin CQFP, Military Grade; ComponentAvailability: Not for New Design
footprint CB164_N (CQFP, 164-Leads, Body 29x29mm; Pitch 0.635mm, Gullwing Leadform, IPC Medium Density)
footprint CB164_L (CQFP, 164-Leads, Body 29x29mm; Pitch 0.635mm, Gullwing Leadform, IPC High Density)
footprint CB164_M (CQFP, 164-Leads, Body 29x29mm; Pitch 0.635mm, Gullwing Leadform, IPC Low Density)
3D model XC3190A-CB164 (164-Pin Ceramic Brazed Quad Flat Pack (CB164))
pins: 1 VCC (power), 2 A13-I/O (io), 3 A6-I/O (io), 4 I/O (io), 5 I/O (io), 6 I/O (io), 7 I/O (io), 8 A12-I/O (io), 9 A7-I/O (io), 10 I/O (io), 11 I/O (io), 12 A11-I/O (io), 13 A8-I/O (io), 14 I/O (io), 15 I/O (io), 16 A10-I/O (io), 17 A9-I/O (io), 18 VCC (power), 19 GND (power), 20 ~{PWRDN} (in), 21 TCLKIN-I/O (io), 22 I/O (io), 23 I/O (io), 24 I/O (io), 25 I/O (io), 26 I/O (io), 27 I/O (io), 28 I/O (io), 29 I/O (io), 30 I/O (io), 31 I/O (io), 32 I/O (io), 33 I/O (io), 34 I/O (io), 35 I/O (io), 36 I/O (io), 37 I/O (io), 38 I/O (io), 39 I/O (io), 40 I/O (io), 41 GND (power), 42 VCC (power), 43 I/O (io), 44 I/O (io), 45 I/O (io), 46 I/O (io), 47 I/O (io), 48 I/O (io), 49 I/O (io), 50 I/O (io), 51 I/O (io), 52 I/O (io), 53 I/O (io), 54 I/O (io), 55 I/O (io), 56 I/O (io), 57 I/O (io), 58 I/O (io), 59 I/O (io), 60 I/O (io), 61 I/O (io), 62 M1~{-RDATA} (out), 63 GND (power), 64 M0-RTRIG (in), 65 VCC (power), 66 M2-I/O (io), 67 HDC-I/O (io), 68 I/O (io), 69 I/O (io), 70 I/O (io), 71 ~{LDC}-I/O (io), 72 I/O (io), 73 I/O (io), 74 I/O (io), 75 I/O (io), 76 I/O (io), 77 I/O (io), 78 I/O (io), 79 I/O (io), 80 I/O (io), 81 ~{INIT}-I/O (io), 82 VCC (power), 83 GND (power), 84 I/O (io), 85 I/O (io), 86 I/O (io), 87 I/O (io), 88 I/O (io), 89 I/O (io), 90 I/O (io), 91 I/O (io), 92 I/O (io), 93 I/O (io), 94 I/O (io), 95 I/O (io), 96 I/O (io), 97 I/O (io), 98 I/O (io), 99 XTL2(IN)-I/O (io), 100 GND (power), 101 ~{RESET} (oe), 102 VCC (power), 103 DONE~{-PG} (out), 104 D7-I/O (io), 105 XTL1(OUT)-I/O (io), 106 I/O (io), 107 I/O (io), 108 I/O (io), 109 D6-I/O (io), 110 I/O (io), 111 I/O (io), 112 I/O (io), 113 I/O (io), 114 I/O (io), 115 D5-I/O (io), 116 ~{CS}0-I/O (io), 117 I/O (io), 118 I/O (io), 119 I/O (io), 120 I/O (io), 121 D4-I/O (io), 122 I/O (io), 123 VCC (power), 124 GND (power), 125 D3-I/O (io), 126 ~{CS}1-I/O (io), 127 I/O (io), 128 I/O (io), 129 I/O (io), 130 I/O (io), 131 D2-I/O (io), 132 I/O (io), 133 I/O (io), 134 I/O (io), 135 I/O (io), 136 I/O (io), 137 D1-I/O (io), 138 RDY~{/BUSY}-~{ RCLK}-I/O (io), 139 I/O (io), 140 I/O (io), 141 I/O (io), 142 I/O (io), 143 D0-DIN-I/O (io), 144 DOUT-I/O (io), 145 CCLK (io), 146 VCC (power), 147 GND (power), 148 A0~{-WS}-I/O (io), 149 A1-CS2-I/O (io), 150 I/O (io), 151 I/O (io), 152 A2-I/O (io), 153 A3-I/O (io), 154 I/O (io), 155 I/O (io), 156 A15-I/O (io), 157 A4-I/O (io), 158 I/O (io), 159 I/O (io), 160 A14-I/O (io), 161 A5-I/O (io), 162 I/O (io), 163 I/O (io), 164 GND (power)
